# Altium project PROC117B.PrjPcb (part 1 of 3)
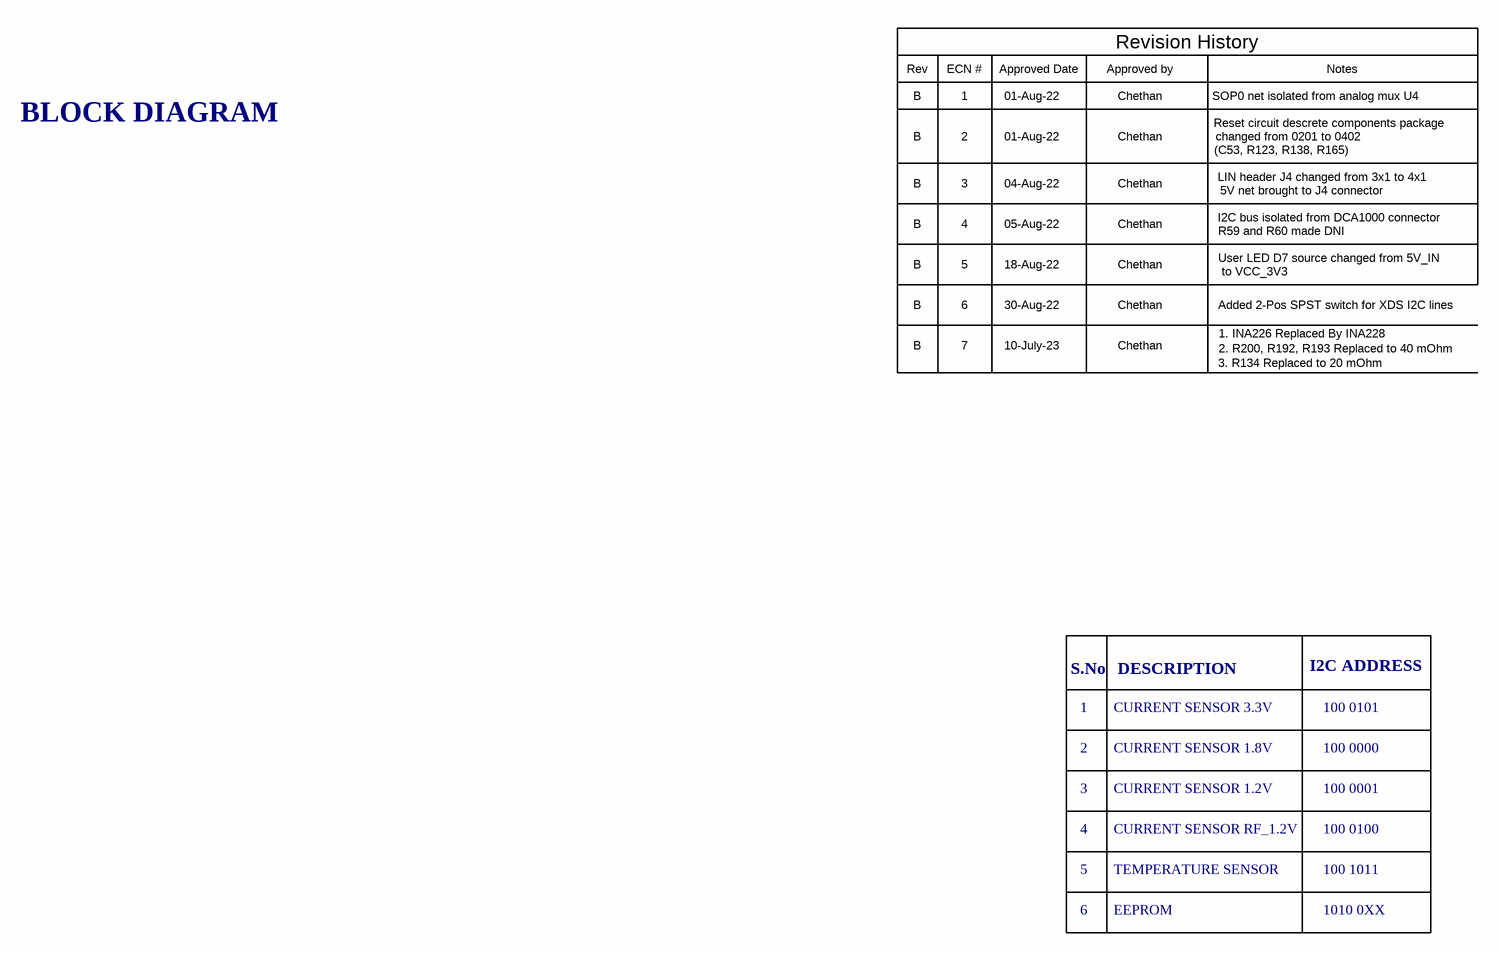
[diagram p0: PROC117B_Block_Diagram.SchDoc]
CopyrightYear: 2022; PCB_Layout: Mistral; PCB_Rev: B; PRJ_Customer: Public Release; PRJ_Engineer: Mistral; PRJ_Number: PROC117; PRJ_Title: xWRL6432BOOST; SCH_Rev: B; TechSupport: http://www.ti.com/support; TID: N/A
16 sheets, 457 parts. Net scope: flat (ports and power ports of the same name join across sheets).
Board file: PROC117B_PCB.PcbDoc
Sheets:
  PROC117B_Block_Diagram.SchDoc
  PROC117B_MUX_Block_Diagram.SchDoc
  PROC117B_Table_Of_Contents.SchDoc
  PROC117B_USB_PWR_DC_Jack_Switch.SchDoc
  PROC117B_DC_Regulators.SchDoc
  PROC117B_xWRL6432_Chip.SchDoc
  PROC117B_Decoupling_caps.SchDoc
  PROC117B_Temp_Current_sensors_EPROM.SchDoc
  PROC117B_QSPI_Flash_LVDS_Driver.SchDoc
  PROC117B_Analog_Mux_SOP_Ctrl.SchDoc
  PROC117B_XDS110_Interface_1A.SchDoc
  PROC117B_XDS110_Interface_1B.SchDoc
  PROC117B_CAN_LIN_PHY_Interface.SchDoc
  PROC117B_DCA1000_Connector_Reset.SchDoc
  PROC117B_LP_BP_Connector.SchDoc
  PROC117B_EVM_Hardware.SchDoc

## Sheet PROC117B_Block_Diagram.SchDoc: BLOCK DIAGRAM
size 431 x 279 mm; Date: Not shown in title block; ApprovedBy: Not shown in title block; CheckedBy: Not shown in title block; Author: Not shown in title block; CompanyName: Not shown in title block; DrawnBy: Mistral; Organization: Not shown in title block; Address1: Not shown in title block; Address2: Not shown in title block; Address3: Not shown in title block; Address4: Not shown in title block; DocumentNumber: 1; Revision: Use project parameter SCH_Rev; SheetNumber: 1; SheetTotal: 16; PageSetup: Record=PageOptions¦CenterHorizontal=True¦CenterVertical=True¦PrintScale=1.00¦XCorrection=1.00¦YCorrection=1.00¦PrintKind=0¦BorderSize=5000000¦LeftOffset=0¦BottomOffset=0¦Orientation=2¦PaperLength=1000¦PaperWidth=1000¦Scale=100¦PaperSource=15¦PrintQuality=600¦MediaType=1¦DitherType=10¦PaperKind=Letter¦PrintScaleMode=1

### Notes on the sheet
- Rev
- B
- ECN #
- 1
- 01-Aug-22
- Approved Date
- Approved by
- Chethan
- Revision History
- SOP0 net isolated from analog mux U4
- Notes
- BLOCK DIAGRAM
- 2
- (C53, R123, R138, R165)
- changed from 0201 to 0402
- Reset circuit descrete components package
- 3
- 4
- 04-Aug-22
- 05-Aug-22
- R59 and R60 made DNI
- 5V net brought to J4 connector
- LIN header J4 changed from 3x1 to 4x1
- I2C bus isolated from DCA1000 connector
- 5
- 6
- 18-Aug-22
- 30-Aug-22
- to VCC_3V3
- User LED D7 source changed from 5V_IN
- Added 2-Pos SPST switch for XDS I2C lines
- 7
- 10-July-23
- 3. R134 Replaced to 20 mOhm
- 1. INA226 Replaced By INA228
- 2. R200, R192, R193 Replaced to 40 mOhm
- S.No
- DESCRIPTION
- I2C ADDRESS
- CURRENT SENSOR 3.3V
- CURRENT SENSOR 1.8V
- 100 0000
- 100 0101
- CURRENT SENSOR 1.2V
- CURRENT SENSOR RF_1.2V
- 100 0001
- 100 0100
- TEMPERATURE SENSOR
- 100 1011
- EEPROM
- 1010 0XX

## Sheet PROC117B_MUX_Block_Diagram.SchDoc: MUX BLOCK DIAGRAM
size 431 x 279 mm; Date: Not shown in title block; ApprovedBy: Not shown in title block; CheckedBy: Not shown in title block; Author: Not shown in title block; CompanyName: Not shown in title block; DrawnBy: Mistral; Engineer: Not shown in title block; Organization: Not shown in title block; Address1: Not shown in title block; Address2: Not shown in title block; Address3: Not shown in title block; Address4: Not shown in title block; DocumentNumber: 2; Revision: Use project parameter SCH_Rev; SheetNumber: 2; SheetTotal: 16; PageSetup: Record=PageOptions¦CenterHorizontal=True¦CenterVertical=True¦PrintScale=1.00¦XCorrection=1.00¦YCorrection=1.00¦PrintKind=0¦BorderSize=5000000¦LeftOffset=0¦BottomOffset=0¦Orientation=2¦PaperLength=1000¦PaperWidth=1000¦Scale=100¦PaperSource=15¦PrintQuality=600¦MediaType=1¦DitherType=10¦PaperKind=Letter¦PrintScaleMode=1
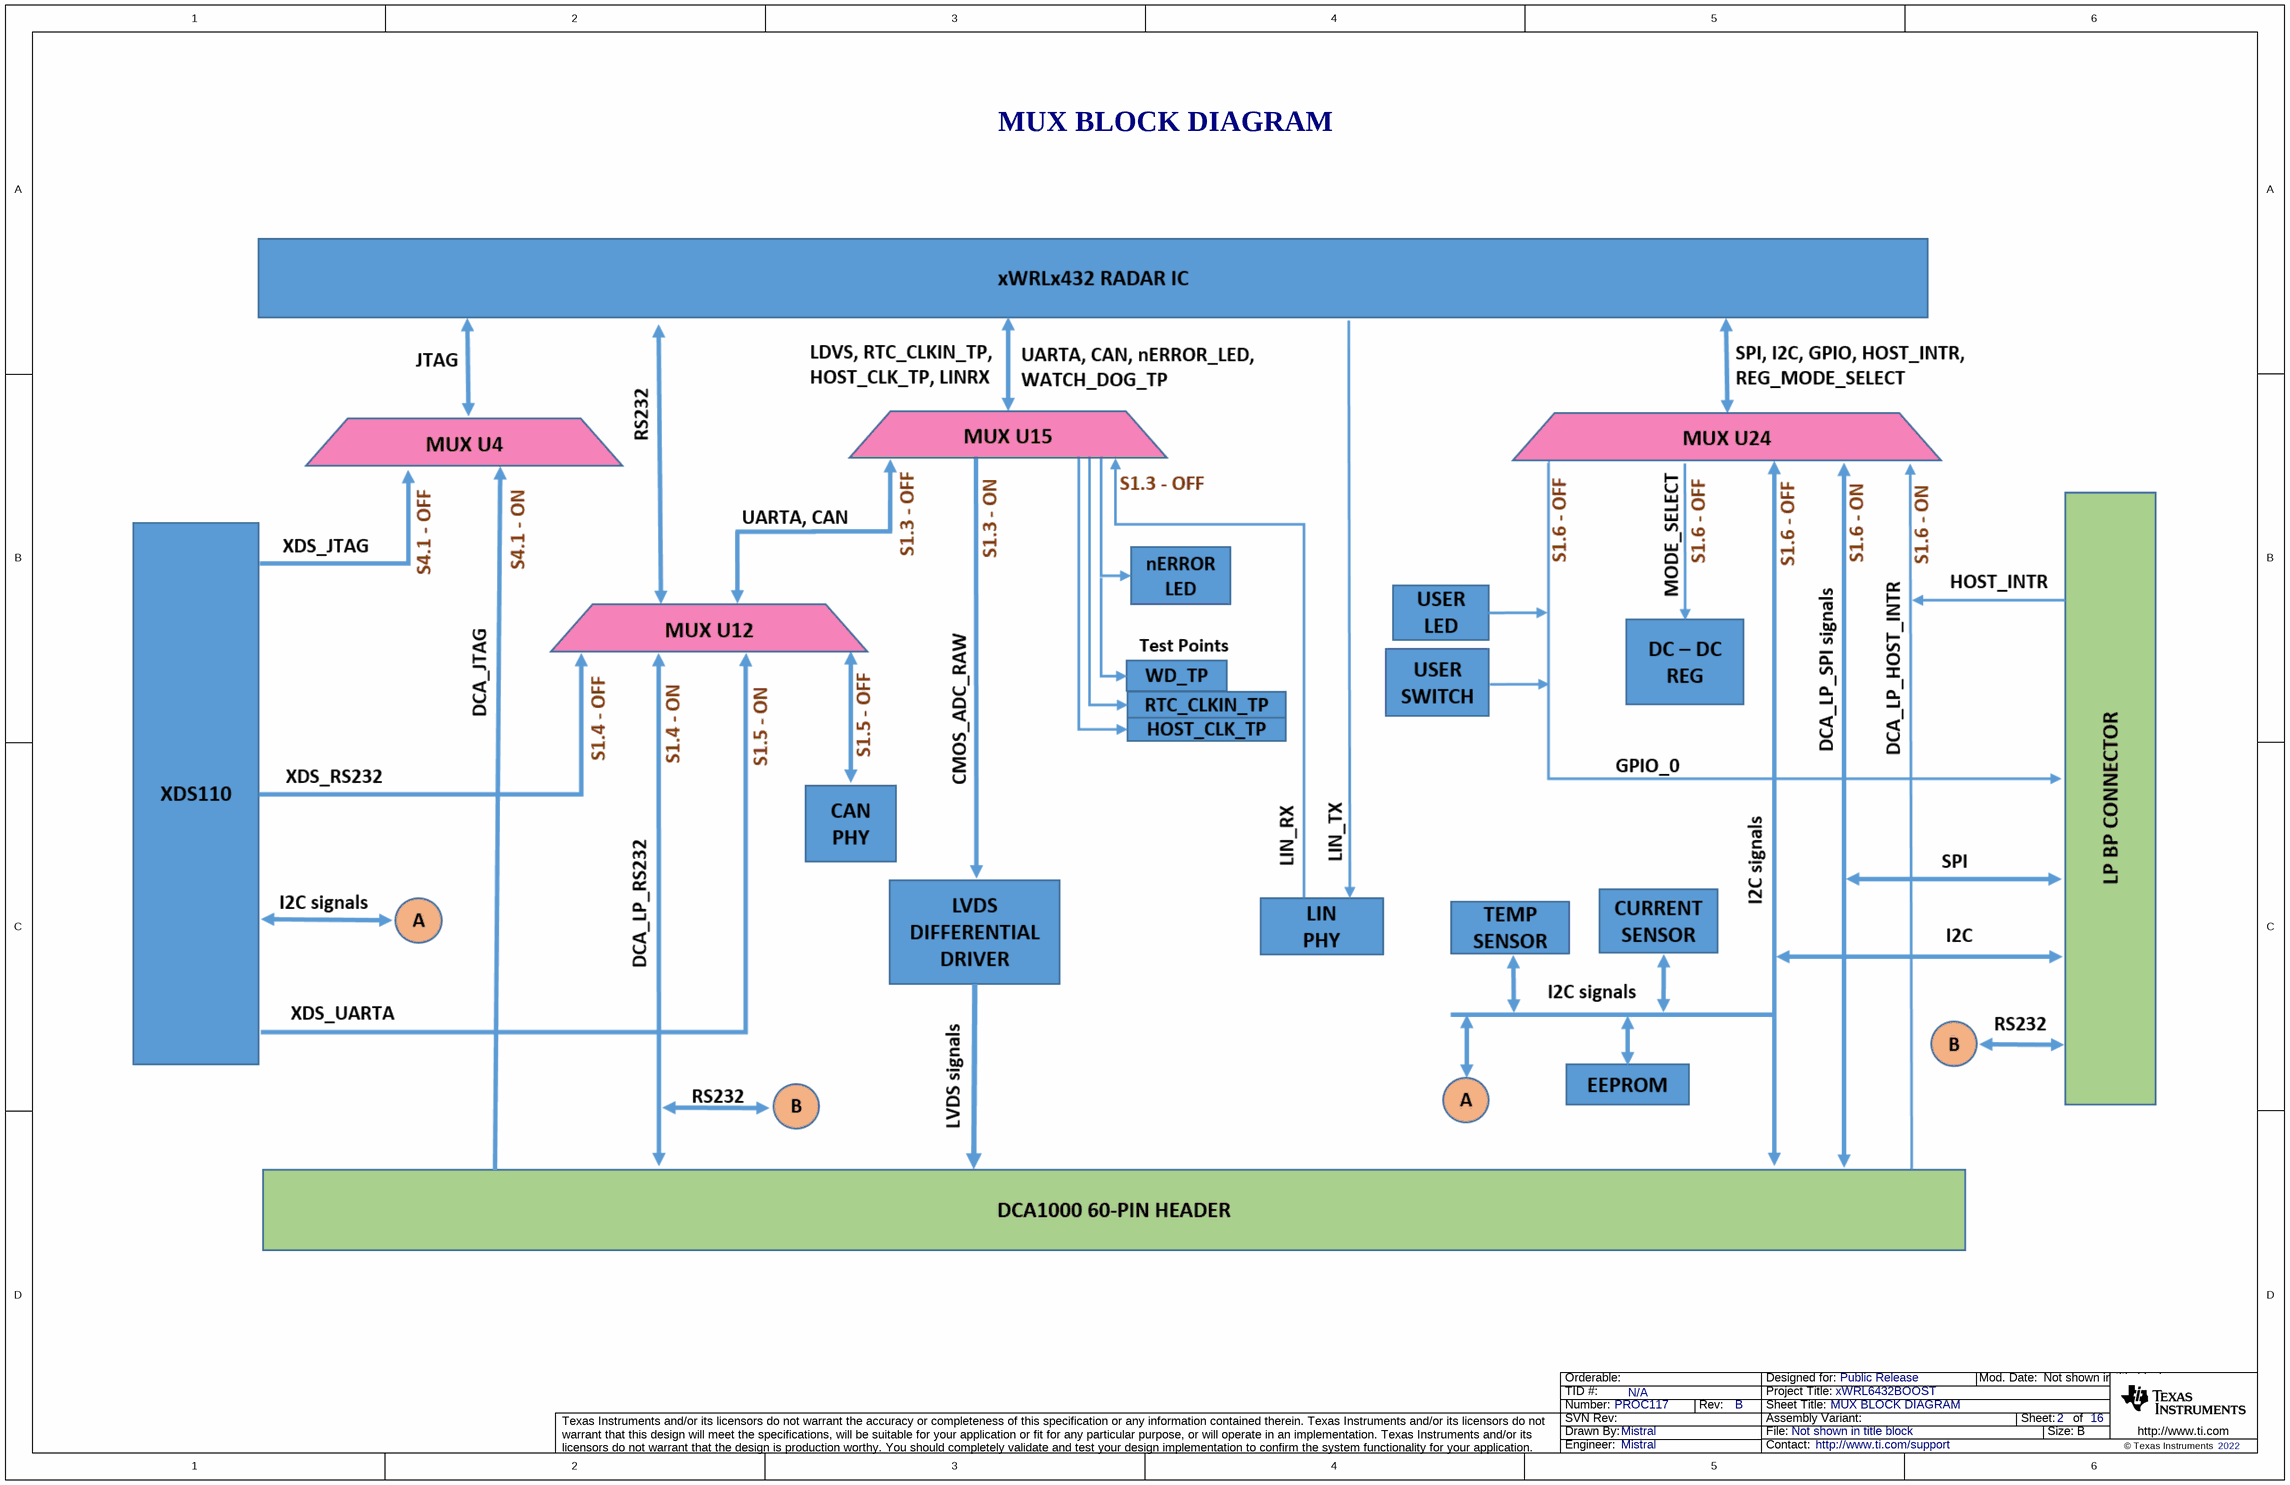
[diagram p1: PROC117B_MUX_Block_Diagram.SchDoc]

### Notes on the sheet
- MUX BLOCK DIAGRAM

## Sheet PROC117B_Table_Of_Contents.SchDoc: TABLE OF CONTENTS
size 431 x 279 mm; Date: Not shown in title block; ApprovedBy: Not shown in title block; CheckedBy: Not shown in title block; Author: Not shown in title block; CompanyName: Not shown in title block; DrawnBy: Mistral; Engineer: Not shown in title block; Organization: Not shown in title block; Address1: Not shown in title block; Address2: Not shown in title block; Address3: Not shown in title block; Address4: Not shown in title block; DocumentNumber: 3; Revision: Use project parameter SCH_Rev; SheetNumber: 3; SheetTotal: 16; PageSetup: Record=PageOptions¦CenterHorizontal=True¦CenterVertical=True¦PrintScale=1.00¦XCorrection=1.00¦YCorrection=1.00¦PrintKind=0¦BorderSize=5000000¦LeftOffset=0¦BottomOffset=0¦Orientation=2¦PaperLength=1000¦PaperWidth=1000¦Scale=100¦PaperSource=15¦PrintQuality=600¦MediaType=1¦DitherType=10¦PaperKind=Letter¦PrintScaleMode=1
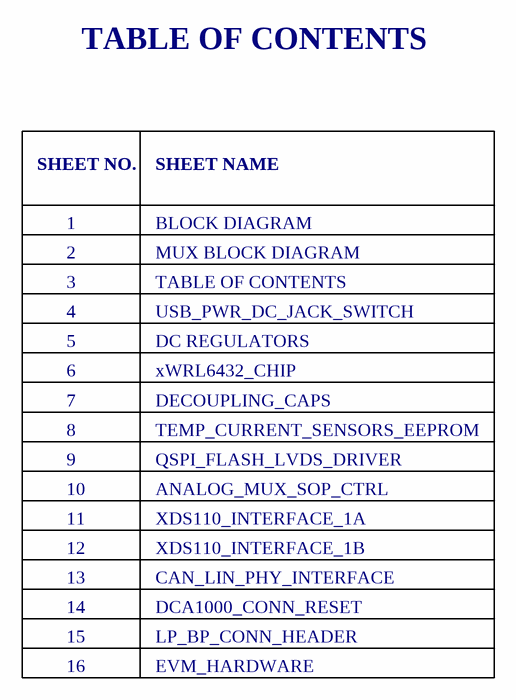
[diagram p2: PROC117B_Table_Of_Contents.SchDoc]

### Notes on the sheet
- TABLE OF CONTENTS
- SHEET NO.
- SHEET NAME
- 1
- 2
- 3
- BLOCK DIAGRAM
- MUX BLOCK DIAGRAM
- 4
- 5
- USB_PWR_DC_JACK_SWITCH
- DC REGULATORS
- 7
- 8
- 6
- DECOUPLING_CAPS
- TEMP_CURRENT_SENSORS_EEPROM
- xWRL6432_CHIP
- 9
- 10
- QSPI_FLASH_LVDS_DRIVER
- ANALOG_MUX_SOP_CTRL
- 11
- 12
- 13
- XDS110_INTERFACE_1B
- XDS110_INTERFACE_1A
- CAN_LIN_PHY_INTERFACE
- 14
- 15
- DCA1000_CONN_RESET
- LP_BP_CONN_HEADER
- 16
- EVM_HARDWARE

## Sheet PROC117B_USB_PWR_DC_Jack_Switch.SchDoc: USB_PWR_DC_JACK_SWITCH
size 431 x 279 mm; Date: Not shown in title block; ApprovedBy: Not shown in title block; CheckedBy: Not shown in title block; Author: Not shown in title block; CompanyName: Not shown in title block; DrawnBy: Mistral; Engineer: Not shown in title block; Organization: Not shown in title block; Address1: Not shown in title block; Address2: Not shown in title block; Address3: Not shown in title block; Address4: Not shown in title block; DocumentNumber: 4; Revision: Use project parameter SCH_Rev; SheetNumber: 4; SheetTotal: 16; PageSetup: Record=PageOptions¦CenterHorizontal=True¦CenterVertical=True¦PrintScale=1.00¦XCorrection=1.00¦YCorrection=1.00¦PrintKind=0¦BorderSize=5000000¦LeftOffset=0¦BottomOffset=0¦Orientation=2¦PaperLength=1000¦PaperWidth=1000¦Scale=100¦PaperSource=15¦PrintQuality=600¦MediaType=1¦DitherType=10¦PaperKind=Letter¦PrintScaleMode=1
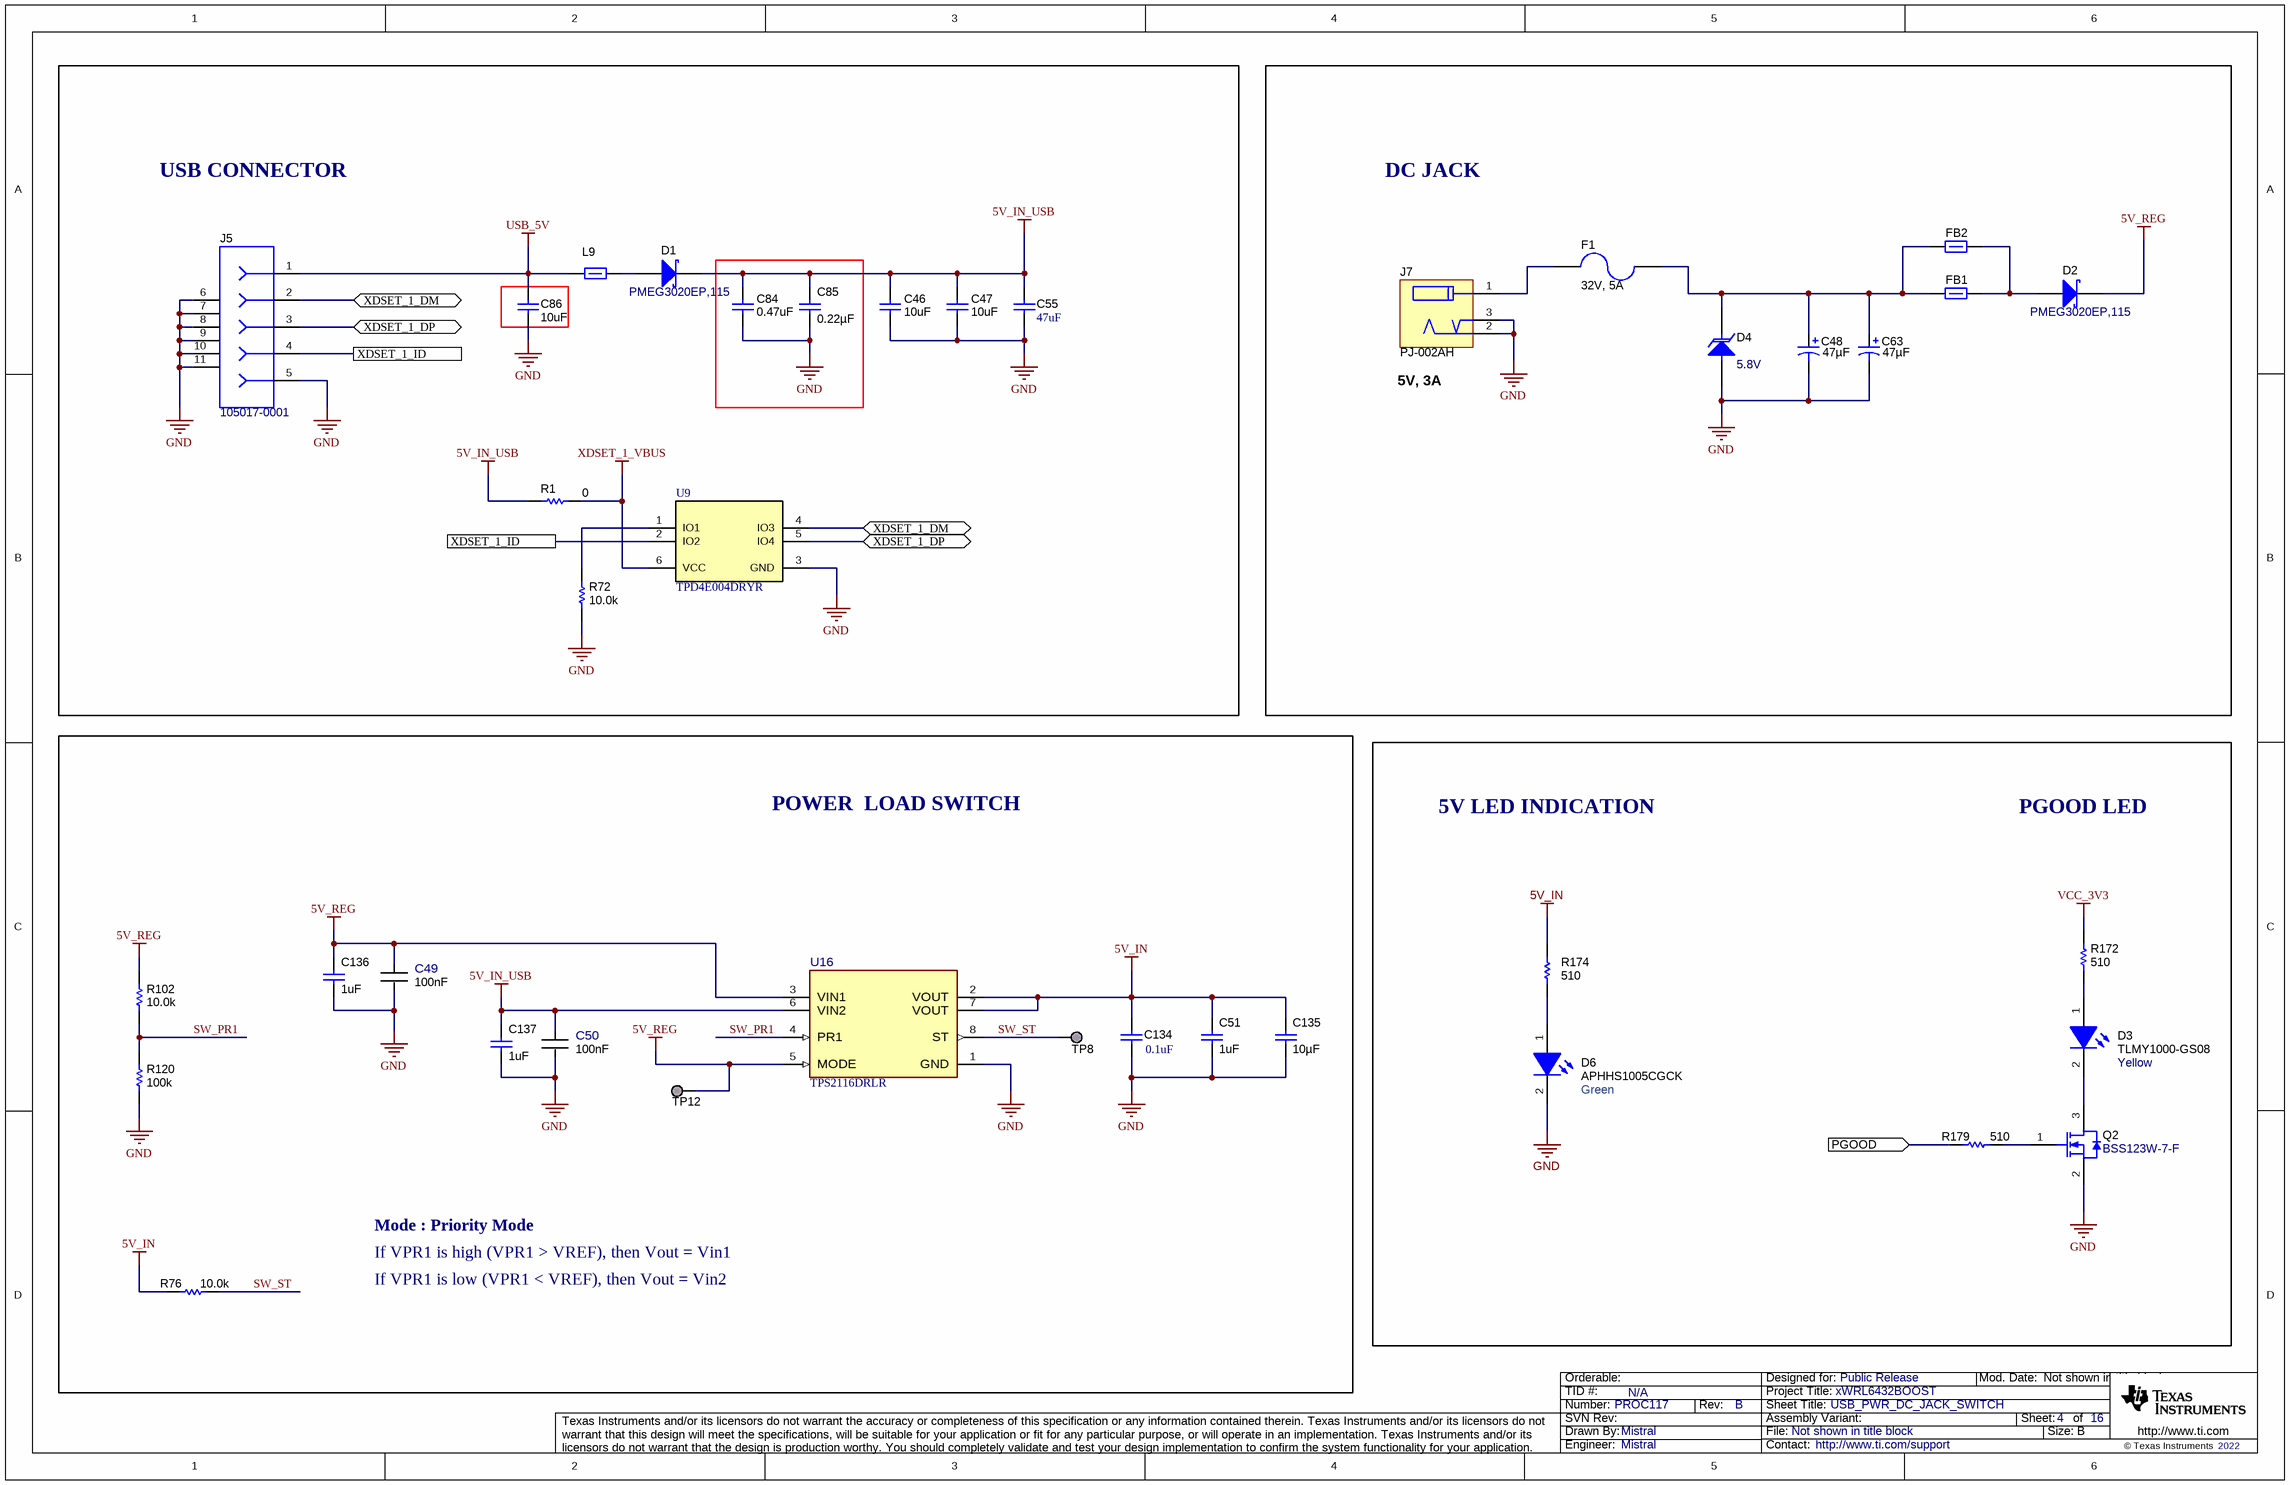
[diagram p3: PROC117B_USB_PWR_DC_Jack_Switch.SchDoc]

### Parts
C46  value 10uF  [0402_070]  (hidden comment: CL05A106MP5NUNC)
C47  value 10uF  [0402_070]  (hidden comment: CL05A106MP5NUNC)
C48  ValueDisplayed: 47µF  [3528-21]  (hidden comment: T491B476K010AT)
C49  value 100nF  [FP-GRM033R6YA104KE14D_0201 (0603 Metric)-IPC_C]  (hidden comment: GRM033R6YA104KE14D)
C50  value 100nF  [FP-GRM033R6YA104KE14D_0201 (0603 Metric)-IPC_C]  (hidden comment: GRM033R6YA104KE14D)
C51  ValueDisplayed: 1uF  [0402L]  (hidden comment: GRT155C81A105KE01D)
C55  ValueDisplayed: 47uF  [1206_180]  (hidden comment: GRM31CR61A476KE15L)
C63  ValueDisplayed: 47µF  [3528-21]  (hidden comment: T491B476K010AT)
C84  ValueDisplayed: 0.47uF  [0402L]  (hidden comment: GCM155C71A474KE36D)
C85  ValueDisplayed: 0.22µF  [0402L]  (hidden comment: GCM155R71C224KE02D)
C86  ValueDisplayed: 10uF  [0603S]  (hidden comment: GRT188R61A106KE13D)
C134  ValueDisplayed: 0.1uF  [0402]  (hidden comment: GCM155R71H104KE02D)
C135  Cap_F: 10µF  [0603]  (hidden comment: GRM188Z71A106MA73D)
C136  ValueDisplayed: 1uF  [0402L]  (hidden comment: GRT155C81A105KE01D)
C137  ValueDisplayed: 1uF  [0402L]  (hidden comment: GRT155C81A105KE01D)
D1  PMEG3020EP,115  [SOD-128]
D2  PMEG3020EP,115  [SOD-128]
D3  TLMY1000-GS08  value Yellow  [TLMx1000_Yellow]
D4  value 5.8V  [SMB]  (hidden comment: SZP6SMB6.8AT3G)
D6  APHHS1005CGCK  Color: Green  [APHHS1005_Green]
F1  32V, 5A  [1206]
FB1  BLM21PG300SH1D  [0805_HV]  (value not drawn)
FB2  BLM21PG300SH1D  [0805_HV]  (value not drawn)
J5  105017-0001  [CONN_105017-0001]
J7  PJ-002AH  [CUI_PJ-002AH]
L9  BLM15PD300SZ1D  [0402L]  (value not drawn)
Q2  BSS123W-7-F  [SOT-323]
R1  ValueDisplayed: 0  [0603]  (hidden comment: MCT06030Z0000ZP500)
R72  ValueDisplayed: 10.0k  [0402L]  (hidden comment: CRCW040210K0FKED)
R76  ValueDisplayed: 10.0k  [0402L]  (hidden comment: CRCW040210K0FKED)
R102  ValueDisplayed: 10.0k  [0402L]  (hidden comment: CRCW040210K0FKED)
R120  value 100k  [0201L]  (hidden comment: CRCW0201100KFKED)
R172  ValueDisplayed: 510  [0402L]  (hidden comment: ERJ-2GEJ511X)
R174  value 510  [0201L]  (hidden comment: RC0201JR-07510RL)
R179  ValueDisplayed: 510  [0402L]  (hidden comment: ERJ-2GEJ511X)
TP8  TESTPOINT  [TP_25MIL-SMT]  (value not drawn)  (no BOM)
TP12  TESTPOINT  [TP_25MIL-SMT]  (value not drawn)  (no BOM)
U9  TPD4E004DRYR  [DRY0006A]
U16  TPS2116DRLR  [DRL0008A-MFG]

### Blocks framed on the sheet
USB CONNECTOR: C46 C47 C55 C84-C86 D1 J5 L9 R1 R72 U9
DC JACK: C48 C63 D2 D4 F1 FB1 FB2 J7
POWER  LOAD SWITCH: C49-C51 C134-C137 R76 R102 R120 TP8 TP12 U16

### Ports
PGOOD (in), XDSET_1_DM (bidir), XDSET_1_DP (bidir), XDSET_1_ID

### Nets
5V_IN: C51.1 C134.1 C135.1 R76.2 R174.1 U16.2(VOUT) U16.7(VOUT)
5V_IN_USB: C46.2 C47.1 C50.1 C55.1 C84.1 C85.2 C137.1 D1.1(K) R1.2 U16.6(VIN2)
5V_REG: C49.1 C136.1 D2.1(K) R102.2 TP12.1 U16.3(VIN1) U16.5(MODE)
GND: C46.1 C47.2 C48.2(-) C49.2 C50.2 C51.2 C55.2 C63.2(-) C84.2 C85.1 C86.1 C134.2 C135.2 C136.2 C137.2 D4.2(A) D6.2(K) J5.5 J5.6 J5.7 J5.8 J5.9 J5.10 J5.11 J7.2 J7.3 Q2.2(S) R72.1 R120.1 U9.3(GND) U16.1(GND)
USB_5V: C86.2 J5.1 L9.1
VCC_3V3: R172.2
XDSET_1_VBUS: R1.1 U9.6(VCC)
PGOOD: R179.1 ; port PGOOD
SW_PR1: R102.1 R120.2 U16.4(PR1)
SW_ST: R76.1 TP8.1 U16.8(ST)
XDSET_1_DM: J5.2 U9.4(IO3) ; port XDSET_1_DM
XDSET_1_DP: J5.3 U9.5(IO4) ; port XDSET_1_DP
XDSET_1_ID: J5.4 U9.2(IO2) ; port XDSET_1_ID
NetC48_1: C48.1(+) C63.1(+) D4.1(K) F1.1 FB1.1 FB2.1
NetD1_2: D1.2(A) L9.2
NetD2_2: D2.2(A) FB1.2 FB2.2
NetD3_1: D3.1(A) R172.1
NetD3_2: D3.2(K) Q2.3(D)
NetD6_1: D6.1(A) R174.2
NetF1_2: F1.2 J7.1
NetQ2_1: Q2.1(G) R179.2
NetR72_2: R72.2 U9.1(IO1)

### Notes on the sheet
- (near J7) 5V, 3A
- 5V LED INDICATION
- PGOOD LED
- Mode : Priority Mode
- If VPR1 is high (VPR1 > VREF), then Vout = Vin1
- If VPR1 is low (VPR1 < VREF), then Vout = Vin2

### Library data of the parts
C46 C47 = CMP-0006339-4: CAP, CERM, 10 uF, 10 V, +/- 20%, X5R, 0402; Manufacturer: Samsung Electro-Mechanics; AEC Category: Q200; AEC Qualified: N; Cap_Case: 0402; Cap_F: 10µF; SizeArea_mm2: 0.5; SizeAreaWB_mm2: 3; SizeX_mm: 1; SizeZ_mm: 0.6; TaMax_C: 85°C; TaMin_C: -55°C; U/M: EA; Value1: Unknown; Value2: 10V
C48 C63 = CMP-0078216-1: CAP, TA, 47 µF, 10 V, +/- 10%, SMD; Manufacturer: Kemet; TaMin_C: -55°C; Polarized: Y; SizeAreaWB_mm2: 17.1; Value: 47uF; TaMax_C: 125°C; SizeZ_mm: 2.1; SizeX_mm: 3.5; SizeY_mm: 2.8; Value2: 10V; SizeArea_mm2: 9.8; CompType: Capacitor; AEC Qualified: N; AEC Category: Q200
C49 C50 = CMP-0086440-1: Cap Ceramic 0.1uF 35V X5R 10% Pad SMD 0201 85C T/R; Manufacturer: Murata Electronics North America; AEC Qualified: No; SizeZ_mm: 0.33mm; Symbol Name: SYM-GRM033R6YA104KE14D; TempCo: 15%
C51 C136 C137 = CMP-0006272-2: CAP, CERM, 1 uF, 10 V, +/- 10%, X6S, 0402; Manufacturer: TDK; Polarized: N; Value: 1uF; U/M: EA; Cap_F: 1µF; Value1: Unknown; VDC_V: 16V; TempCo: X5R; TaMin_C: -55°C; TaMax_C: 85°C; Cap_Case: 0402; SizeArea_mm2: 0.5; SizeAreaWB_mm2: 3; SizeX_mm: 1; SizeZ_mm: 0.6; AEC Category: Q200
C55 = CMP-0008944-2: CAP, CERM, 47 uF, 10 V, +/- 10%, X5R, 1206; Manufacturer: MuRata; TaMin_C: -55°C; Polarized: N; SizeAreaWB_mm2: 10.92; Value1: Unknown; U/M: EA; Value: 47uF; TaMax_C: 85°C; SizeZ_mm: 1.8; SizeX_mm: 3.2; SizeY_mm: 1.6; Cap_Case: 1206; Value2: 10V; SizeArea_mm2: 5.12; Cap_F: 47µF; AEC Category: Q200
C84 = CMP-0064967-2: CAP, CERM, 0.47 uF, 10 V,+/- 10%, X7S, 0402; Manufacturer: MuRata; Polarized: N; Value: 0.47uF; U/M: EA; Cap_F: 470nF; Value1: Unknown; VDC_V: 10V; TaMin_C: -55°C; TaMax_C: 125°C; Cap_Case: 0402; SizeArea_mm2: 0.5; SizeAreaWB_mm2: 3; SizeX_mm: 1; SizeZ_mm: 0.6; AEC Category: Q200
C85 = CMP-0078265-1: CAP, CERM, 0.22 µF, 16 V,+/- 10%, X7R, AEC-Q200 Grade 1, 0402; Manufacturer: MuRata; TaMin_C: -55°C; Polarized: N; SizeAreaWB_mm2: 3; U/M: EA; Value: 0.22uF; TaMax_C: 125°C; SizeZ_mm: 0.6; SizeX_mm: 1; SizeY_mm: 0.5; Cap_Case: 0402; Value2: 16V; CompType: Capacitor; AEC Qualified: Y; Cap_F: 220nF; AEC Category: Q200
C86 = CMP-0007497-5: CAP, CERM, 10 uF, 10 V, +/- 10%, X5R, 0603; Manufacturer: MuRata; Polarized: N; Value: 10uF; U/M: EA; Cap_F: 10µF; Tolerance_%: 20%; Value1: Unknown; VDC_V: 10V; TempCo: X7R; TaMin_C: -55°C; TaMax_C: 125°C; Cap_Case: 0603; SizeArea_mm2: 1.28; SizeAreaWB_mm2: 4.68; SizeX_mm: 1.6; SizeY_mm: 0.8; SizeZ_mm: 1; AEC Category: Q200
C134 = CMP-0006356-2: CAP, CERM, 0.1 uF, 50 V, +/- 10%, X7R, AEC-Q200 Grade 1, 0402; Manufacturer: MuRata; TaMin_C: -55°C; Polarized: N; SizeAreaWB_mm2: 3; Value1: Unknown; U/M: EA; Value: 0.1uF; TaMax_C: 125°C; SizeZ_mm: 0.6; SizeX_mm: 1; SizeY_mm: 0.5; Value2: 50V; AEC Qualified: Y; Cap_F: 100nF; AEC Category: Q200
C135 = CMP-0007497-5: CAP, CERM, 10 uF, 10 V, +/- 20%, X7R, 0603; Manufacturer: MuRata; TaMin_C: -55°C; Polarized: N; SizeAreaWB_mm2: 4.68; Value1: Unknown; U/M: EA; Value: 10uF; TaMax_C: 125°C; SizeZ_mm: 1; SizeX_mm: 1.6; SizeY_mm: 0.8; Value2: 10V; SizeArea_mm2: 1.28; AEC Category: Q200
D1 D2 = CMP-0078758-2: Diode, Schottky, 30 V, 2 A, AEC-Q101, SOD-128; Manufacturer: Nexperia; Value2: 0.36V; SizeAreaWB_mm2: 19.6; Io_A: 2A; Value: 30V; AEC Qualified: Y; TJmax_C: 150°C; SizeX_mm: 4.6; AEC Category: Q101; SizeY_mm: 2.5; SizeArea_mm2: 11.5; Vf_V: 3.6dV; SizeZ_mm: 1.1
D3 = CMP-0078196-2: LED, Yellow, SMD; Manufacturer: Vishay-Semiconductor; Tjmax_C: 120°C; SizeAreaWB_mm2: 4.68; Vr_V: 6V; Power_TotalModule: 40mW; Angle: 160; SizeArea_mm2: 1.28; Ir_A: 10µA; SizeZ_mm: 0.65; Io_A: 2mA; Vf_V: 1.8V; SizeY_mm: 0.8; Value1: .04W; SizeX_mm: 1.6; Type: AlInGaP
D4 = CMP-0078243-3: Diode, TVS, Uni, 5.8 V, 10.5 Vc, AEC-Q101, SMB; Manufacturer: Littelfuse; SizeAreaWB_mm2: 44.156; Value1: 0.55W; RJA_CperW: 226; SizeZ_mm: 2.6; SizeX_mm: 5.6; SizeY_mm: 3.81; SizeArea_mm2: 21.336; AEC Qualified: Y; AEC Category: Q101; Vc: 10.5V
D6 = CMP-0067682-2: LED, Green, SMD; Manufacturer: Kingbright; Angle: 120.0; Power_TotalModule: 75mW; SizeZ_mm: 0.6; Vf_V: 2.1V; Vr_V: 5V; Io_A: 20mA; Ir_A: 10µA; SizeArea_mm2: 0.5; SizeAreaWB_mm2: 3.0; SizeX_mm: 1.0; Tjmax_C: 85°C; Value1: 0.075W
F1 = CMP-0003458-2: Fuse, 5 A, 32VAC/VDC, SMD; Manufacturer: Littelfuse; PartNumber: 0440005.WR; SizeAreaWB_mm2: 10.92; Interrupt_AC: 50A; SizeZ_mm: 1.35; SizeX_mm: 3.2; SizeY_mm: 1.6; SizeArea_mm2: 5.12; Rtyp_Ohm: 0.012; MeltingTyp: 4.761
FB1 = CMP-0003364-1: Ferrite Bead, 30 ohm @ 100 MHz, 4 A, 0805; Manufacturer: MuRata; ZTyp@100MHz_Ohm: 30; SizeAreaWB_mm2: 6.75; DCR_ohm: 0.014; Value1: 0.014 ohm; Value: 30 ohm; Imax_A: 4A; SizeZ_mm: 1.45; SizeX_mm: 2; SizeY_mm: 1.25; SizeArea_mm2: 2.5; INSTALLATION: DNP
FB2 = CMP-0003364-1: Ferrite Bead, 30 ohm @ 100 MHz, 4 A, 0805; Manufacturer: MuRata; ZTyp@100MHz_Ohm: 30; SizeAreaWB_mm2: 6.75; DCR_ohm: 0.014; Value1: 0.014 ohm; Value: 30 ohm; Imax_A: 4A; SizeZ_mm: 1.45; SizeX_mm: 2; SizeY_mm: 1.25; SizeArea_mm2: 2.5
J5 = CMP-0055293-1: Connector, Receptacle, Micro-USB Type B, R/A, Bottom Mount SMT; Manufacturer: Molex; CNHeader: FALSE; CompType: USB; CT: TRUE; Gender: Female; Green_Lifecycle: Active; Green_REACh: Passed
J7 = CMP-0078270-1: DC POWER JACK, R/A, TH; Manufacturer: CUI Inc.; Gender: Female; Cert_UL: Y; Current_A: 5A; Voltage_V: 4.5-5.5V; Green_REACh: Incomplete; Green_Lifecycle: Not Set
L9 = CMP-0078934-1: Inductor, Ferrite Bead, Ferrite, 2.2 A, 0.035 ohm, AEC-Q200 Grade 1, SMD; Manufacturer: MuRata; AEC Category: Q200; AEC Grade: 1; AEC Qualified: Y; DCR_ohm: 0.035; Imax_A: 2.2A; SizeArea_mm2: 0.5; SizeAreaWB_mm2: 3; SizeZ_mm: 0.6
Q2 = CMP-0000948-2: MOSFET, N-CH, 100 V, 0.17 A, SOT-323; Alternate Manufacturer: None; Manufacturer: Diodes Inc.; SizeZ_mm: 1.1; ChType: N; Value1: 1; VdsMax_V: 100V; SizeX_mm: 2.2; Vgs_V: 20V; Value: 100V; Rdson45_ohm: 10; SizeArea_mm2: 4.84; AEC Category: Q101; IdsMax_A: 1.7dA; SizeAreaWB_mm2: 10.24; U/M: EA
R1 = CMP-0025884-3: RES, 0, 5%, 0.125 W, 0603; Manufacturer: Vishay/Beyschlag; Power_W: 125mW; TempCo: ppm/C; Value_Code: 0000; U/M: EA; Value: 0; EIA_Code: E24; SizeX_mm: 1.6; SizeY_mm: 0.8; SizeZ_mm: 1; Value2: 0.125W; SizeArea_mm2: 1.28; AEC Qualified: N; AEC Category: Q200
R72 R76 R102 = CMP-0025958-3: RES, 10.0 k, 1%, 0.063 W, AEC-Q200 Grade 0, 0402; Manufacturer: Vishay-Dale; Power_W: 63mW; TempCo: 100 ppm/C; Value_Code: 10k0; Value: 10.0k; EIA_Code: E96; Res_ohm: 10k; SizeX_mm: 1; SizeY_mm: 0.5; SizeZ_mm: 0.6; Value2: 0.063W; AEC Qualified: Y; VDC_V: 50V; AEC Category: Q200; AEC Grade: 0
R120 = CMP-0027261-3: RES, 100 k, 1%, 0.05 W, 0201; Manufacturer: Vishay-Dale; AEC Category: Q200; AEC Qualified: N; EIA_Code: E96; Power_W: 50mW; SizeArea_mm2: 0.18; SizeX_mm: 0.6; SizeY_mm: 0.3; SizeZ_mm: 0.26; TempCo: 100 ppm/C; Value2: 0.05W; VDC_V: 30V
R172 R179 = CMP-0078212-1: RES, 510, 5%, 0.1 W, AEC-Q200 Grade 0, 0402; Manufacturer: Panasonic; Value_Code: 510R; SizeArea_mm2: 0.5; AEC Qualified: Y; AEC Category: Q200; Value: 510; SizeZ_mm: 0.6; EIA_Code: E24; TempCo: 200 ppm/C; AEC Grade: 0; Power_W: 100mW; VDC_V: 50V; Value2: 0.1W; U/M: EA; SizeX_mm: 1
R174 = CMP-0027137-1: RES, 510, 5%, 0.05 W, 0201; Manufacturer: Yageo America; AEC Category: Q200; AEC Qualified: N; EIA_Code: E24; Power_W: 50mW; SizeArea_mm2: 0.18; SizeX_mm: 0.6; SizeY_mm: 0.3; SizeZ_mm: 0.26; TempCo: 200 ppm/C; U/M: EA; Value2: 0.05W; Value_Code: 510R; VDC_V: 25V
TP8 TP12 = CMP-0078143-3: TEST POINT.  No entry in BOM.
U9 = CMP-0043115-3: 4-Channel ESD Protection Array for High-Speed Data Interfaces, DRY0006A (USON-6); Manufacturer: Texas Instruments; IO Leakage Current(nA): 1; USB High Speed: TRUE; IO Capacitance(Typ)(pF): 1.6; Eco-Plan: Green (RoHS & no Sb/Br); IEC 61000-4-2 Contact(+/- kV): 8; Breakdown Voltage(Min)(V): 6; IEC 61000-4-2 Air-Gap(+/- kV): 12; AEC Category: Q200; AEC Qualified: N; CompType: IC; SizeAreaWB_mm2: 4.9; SizeArea_mm2: 1.45; SizeX_mm: 1.0; SizeZ_mm: 0.6; Rating: Catalog
U16 = CMP-0088593-2: 1.6 V to 5 V, 2.5-A Low IQ Power Mux With Manual and Automatic Switchover; Manufacturer: Texas Instruments; Max Supply Voltage: 5.5V; TaMax_C: +125°C; Output Voltage: 0-5.5V; CompType: IC; Min Supply Voltage: 1.6V; TaMin_C: -55°C; SizeZ_mm: 0.6mm; AEC Category: Q200; Nominal Supply Current: 0.5-1uA; Number Of Outputs: 1; Standoff Height: 0mm; AEC Qualified: No

## Sheet PROC117B_DC_Regulators.SchDoc: DC_REGULATORS
size 431 x 279 mm; Date: Not shown in title block; ApprovedBy: Not shown in title block; CheckedBy: Not shown in title block; Author: Not shown in title block; CompanyName: Not shown in title block; DrawnBy: Mistral; Engineer: Not shown in title block; Organization: Not shown in title block; Address1: Not shown in title block; Address2: Not shown in title block; Address3: Not shown in title block; Address4: Not shown in title block; DocumentNumber: 5; Revision: Use project parameter SCH_Rev; SheetNumber: 5; SheetTotal: 16; PageSetup: Record=PageOptions¦CenterHorizontal=True¦CenterVertical=True¦PrintScale=1.00¦XCorrection=1.00¦YCorrection=1.00¦PrintKind=0¦BorderSize=5000000¦LeftOffset=0¦BottomOffset=0¦Orientation=2¦PaperLength=1000¦PaperWidth=1000¦Scale=100¦PaperSource=15¦PrintQuality=600¦MediaType=1¦DitherType=10¦PaperKind=Letter¦PrintScaleMode=1
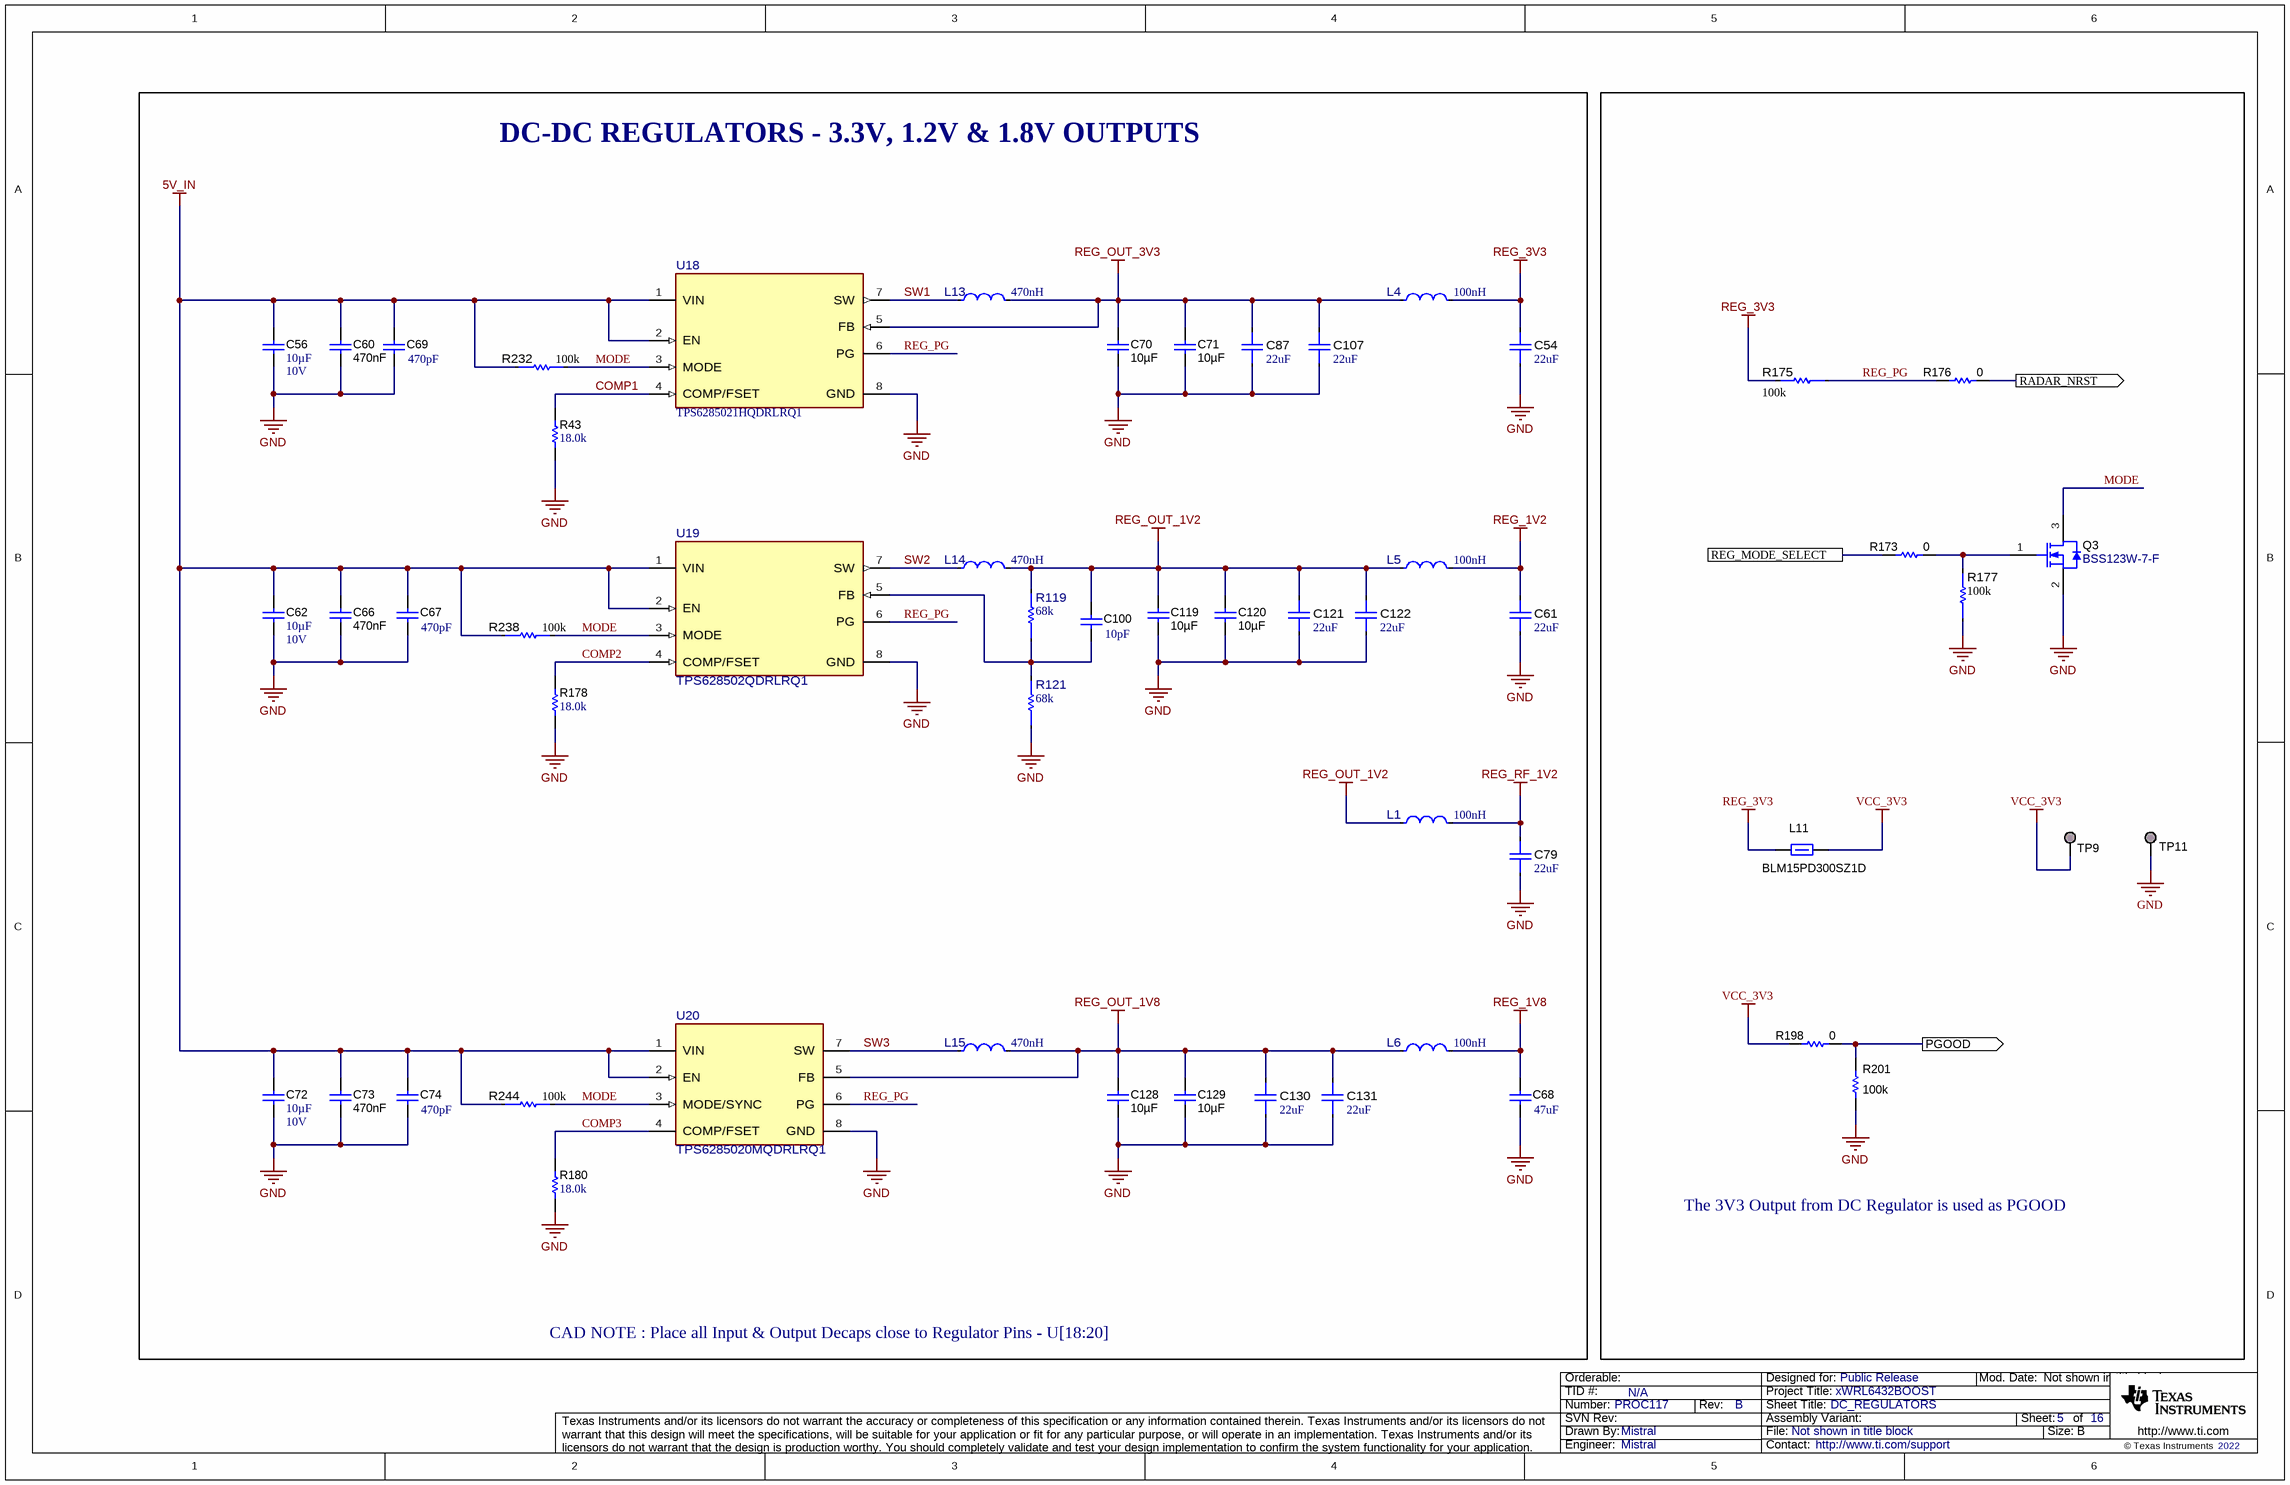
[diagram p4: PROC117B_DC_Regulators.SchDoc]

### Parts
C54  ValueDisplayed: 22uF  [FP-GRM31CR70J226ME19K_1206-MFG]  (hidden comment: GRM31CR70J226ME19K)
C56  Cap_F: 10µF  VDC_V: 10V  [0603_HV]  (hidden comment: GRM188Z71A106MA73D)
C60  Cap_F: 470nF  [0603S]  (hidden comment: GRM188R71C474KA88D)
C61  ValueDisplayed: 22uF  [FP-GRM31CR70J226ME19K_1206-MFG]  (hidden comment: GRM31CR70J226ME19K)
C62  Cap_F: 10µF  VDC_V: 10V  [0603_HV]  (hidden comment: GRM188Z71A106MA73D)
C66  Cap_F: 470nF  [0603S]  (hidden comment: GRM188R71C474KA88D)
C67  ValueDisplayed: 470pF  [0402L]  (hidden comment: GRM1555C1H471JA01D)
C68  ValueDisplayed: 47uF  [1206_180]  (hidden comment: GRM31CR60J476ME19L)
C69  ValueDisplayed: 470pF  [0402L]  (hidden comment: GRM1555C1H471JA01D)
C70  Cap_F: 10µF  [0603]  (hidden comment: GRM188Z71A106MA73D)
C71  Cap_F: 10µF  [0603]  (hidden comment: GRM188Z71A106MA73D)
C72  Cap_F: 10µF  VDC_V: 10V  [0603_HV]  (hidden comment: GRM188Z71A106MA73D)
C73  Cap_F: 470nF  [0603S]  (hidden comment: GRM188R71C474KA88D)
C74  ValueDisplayed: 470pF  [0402L]  (hidden comment: GRM1555C1H471JA01D)
C79  ValueDisplayed: 22uF  [FP-GRM31CR70J226ME19K_1206-MFG]  (hidden comment: GRM31CR70J226ME19K)
C87  ValueDisplayed: 22uF  [FP-GRM31CR70J226ME19K_1206-MFG]  (hidden comment: GRM31CR70J226ME19K)
C100  ValueDisplayed: 10pF  [0402]  (hidden comment: CGA2B2C0G1H100D050BA)
C107  ValueDisplayed: 22uF  [FP-GRM31CR70J226ME19K_1206-MFG]  (hidden comment: GRM31CR70J226ME19K)
C119  Cap_F: 10µF  [0603]  (hidden comment: GRM188Z71A106MA73D)
C120  Cap_F: 10µF  [0603]  (hidden comment: GRM188Z71A106MA73D)
C121  ValueDisplayed: 22uF  [FP-GRM31CR70J226ME19K_1206-MFG]  (hidden comment: GRM31CR70J226ME19K)
C122  ValueDisplayed: 22uF  [FP-GRM31CR70J226ME19K_1206-MFG]  (hidden comment: GRM31CR70J226ME19K)
C128  Cap_F: 10µF  [0603]  (hidden comment: GRM188Z71A106MA73D)
C129  Cap_F: 10µF  [0603]  (hidden comment: GRM188Z71A106MA73D)
C130  ValueDisplayed: 22uF  [FP-GRM31CR70J226ME19K_1206-MFG]  (hidden comment: GRM31CR70J226ME19K)
C131  ValueDisplayed: 22uF  [FP-GRM31CR70J226ME19K_1206-MFG]  (hidden comment: GRM31CR70J226ME19K)
L1  Ind_H: 100nH  [FP-LQM2MPZR10MJHL_0806 (2016)-MFG]  (hidden comment: LQM2MPZR10MJHL)
L4  Ind_H: 100nH  [FP-LQM2MPZR10MJHL_0806 (2016)-MFG]  (hidden comment: LQM2MPZR10MJHL)
L5  Ind_H: 100nH  [FP-LQM2MPZR10MJHL_0806 (2016)-MFG]  (hidden comment: LQM2MPZR10MJHL)
L6  Ind_H: 100nH  [FP-LQM2MPZR10MJHL_0806 (2016)-MFG]  (hidden comment: LQM2MPZR10MJHL)
L11  BLM15PD300SZ1D  [0402L]
L13  Ind_H: 470nH  [FP-DFE201210U-R47M=P2_0805 (2012)-MFG]  (hidden comment: DFE201210U-R47M=P2)
L14  Ind_H: 470nH  [FP-DFE201210U-R47M=P2_0805 (2012)-MFG]  (hidden comment: DFE201210U-R47M=P2)
L15  Ind_H: 470nH  [FP-DFE201210U-R47M=P2_0805 (2012)-MFG]  (hidden comment: DFE201210U-R47M=P2)
Q3  BSS123W-7-F  [SOT-323]
R43  ValueDisplayed: 18.0k  [0402L]  (hidden comment: CRCW040218K0FKED)
R119  Res_ohm: 68k  [FP-RMCF0402FT68K0_0402-MFG]  (hidden comment: RMCF0402FT68K0)
R121  Res_ohm: 68k  [FP-RMCF0402FT68K0_0402-MFG]  (hidden comment: RMCF0402FT68K0)
R173  Res_ohm: 0  [FP-RC0201JR-070RL_0201 (0603 Metric)-IPC_C]  (hidden comment: RC0201JR-070RL)
R175  Res_ohm: 100k  [FP-CRCW0402100KFKEDC_0402-IPC_B]  (hidden comment: CRCW0402100KFKEDC)
R176  Res_ohm: 0  [FP-RC0201JR-070RL_0201 (0603 Metric)-IPC_C]  (hidden comment: RC0201JR-070RL)
R177  Res_ohm: 100k  [FP-CRCW0402100KFKEDC_0402-IPC_B]  (hidden comment: CRCW0402100KFKEDC)
R178  ValueDisplayed: 18.0k  [0402L]  (hidden comment: CRCW040218K0FKED)
R180  ValueDisplayed: 18.0k  [0402L]  (hidden comment: CRCW040218K0FKED)
R198  Res_ohm: 0  [FP-RC0201JR-070RL_0201 (0603 Metric)-MFG]  (hidden comment: RC0201JR-070RL)
R201  value 100k  [0201L]  (hidden comment: CRCW0201100KFKED)
R232  Res_ohm: 100k  [FP-CRCW0402100KFKEDC_0402-IPC_B]  (hidden comment: CRCW0402100KFKEDC)
R238  Res_ohm: 100k  [FP-CRCW0402100KFKEDC_0402-IPC_B]  (hidden comment: CRCW0402100KFKEDC)
R244  Res_ohm: 100k  [FP-CRCW0402100KFKEDC_0402-IPC_B]  (hidden comment: CRCW0402100KFKEDC)
TP9  TESTPOINT  [TP_25MIL-SMT]  (value not drawn)  (no BOM)
TP11  TESTPOINT  [TP_VIA_060RND040]  (value not drawn)  (no BOM)
U18  TPS6285021HQDRLRQ1  [DRL0008A-MFG]
U19  TPS628502QDRLRQ1  [DRL0008A-MFG]
U20  TPS6285020MQDRLRQ1  [DRL0008A-MFG]

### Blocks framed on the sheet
DC-DC REGULATORS - 3.3V, 1.2V & 1.8V OUTPUTS: C54 C56 C60-C62 C66-C74 C79 C87 C100 C107 C119-C122 C128-C131 L1 L4-L6 L13-L15 R43 R119 R121 R178 R180 R232 R238 R244 U18-U20
The 3V3 Output from DC Regulator is used as PGOOD: L11 Q3 R173 R175-R177 R198 R201 TP9 TP11

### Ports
PGOOD (out), RADAR_NRST (out), REG_MODE_SELECT

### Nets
5V_IN: C56.1 C60.1 C62.1 C66.1 C67.1 C69.1 C72.1 C73.1 C74.1 R232.1 R238.1 R244.1 U18.1(VIN) U18.2(EN) U19.1(VIN) U19.2(EN) U20.1(VIN) U20.2(EN)
GND: C54.1 C56.2 C60.2 C61.1 C62.2 C66.2 C67.2 C68.1 C69.2 C70.2 C71.2 C72.2 C73.2 C74.2 C79.1 C87.1 C107.1 C119.2 C120.2 C121.1 C122.1 C128.2 C129.2 C130.1 C131.1 Q3.2(S) R43.1 R121.1 R177.1 R178.1 R180.1 R201.1 TP11.1 U18.8(GND) U19.8(GND) U20.8(GND)
REG_1V2: C61.2 L5.2
REG_1V8: C68.2 L6.2
REG_3V3: C54.2 L4.2 L11.1 R175.2
REG_OUT_1V2: C100.1 C119.1 C120.1 C121.2 C122.2 L1.1 L5.1 L14.2 R119.2
REG_OUT_1V8: C128.1 C129.1 C130.2 C131.2 L6.1 L15.2 U20.5(FB)
REG_OUT_3V3: C70.1 C71.1 C87.2 C107.2 L4.1 L13.2 U18.5(FB)
REG_RF_1V2: C79.2 L1.2
VCC_3V3: L11.2 R198.2 TP9.1
COMP1: R43.2 U18.4(COMP/FSET)
COMP2: R178.2 U19.4(COMP/FSET)
COMP3: R180.2 U20.4(COMP/FSET)
MODE: Q3.3(D) R232.2 R238.2 R244.2 U18.3(MODE) U19.3(MODE) U20.3(MODE/SYNC)
PGOOD: R198.1 R201.2 ; port PGOOD
RADAR_NRST: R176.1 ; port RADAR_NRST
REG_MODE_SELECT: R173.2 ; port REG_MODE_SELECT
REG_PG: R175.1 R176.2 U18.6(PG) U19.6(PG) U20.6(PG)
SW1: L13.1 U18.7(SW)
SW2: L14.1 U19.7(SW)
SW3: L15.1 U20.7(SW)
NetC100_2: C100.2 R119.1 R121.2 U19.5(FB)
NetQ3_1: Q3.1(G) R173.1 R177.2

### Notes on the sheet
- CAD NOTE : Place all Input & Output Decaps close to Regulator Pins - U[18:20]

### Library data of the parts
C54 C61 C79 C87 C107 C121 C122 C130 C131 = CMP-0092150-1: Chip Multilayer Ceramic Capacitors for General Purpose, 1206, 22uF, X7R, 15%, 20%, 6.3V; Manufacturer: Murata; SizeZ_mm: 1.8mm; AEC Qualified: No; Value: 22µF
C56 C62 C72 = CMP-0007497-5: CAP, CERM, 10 uF, 10 V, +/- 20%, X7R, 0603; Manufacturer: MuRata; TaMin_C: -55°C; Polarized: N; SizeAreaWB_mm2: 4.68; Value1: Unknown; U/M: EA; Value: 10uF; TaMax_C: 125°C; SizeZ_mm: 1; SizeX_mm: 1.6; SizeY_mm: 0.8; Cap_Case: 0603; SizeArea_mm2: 1.28; AEC Category: Q200
C60 C66 C73 = CMP-0007398-4: CAP, CERM, 0.47 uF, 16 V, +/- 10%, X7R, 0603; Manufacturer: MuRata; TaMin_C: -55°C; Polarized: N; SizeAreaWB_mm2: 4.68; Value1: Unknown; U/M: EA; Value: 0.47uF; TaMax_C: 125°C; SizeZ_mm: 1; SizeX_mm: 1.6; SizeY_mm: 0.8; Cap_Case: 0603; Value2: 16V; SizeArea_mm2: 1.28; AEC Category: Q200
C67 C69 C74 = CMP-0006470-2: CAP, CERM, 470 pF, 50 V, +/- 5%, C0G/NP0, 0402; Manufacturer: MuRata; TaMin_C: -55°C; Polarized: N; SizeAreaWB_mm2: 3; Value1: Unknown; U/M: EA; Value: 470pF; TaMax_C: 125°C; SizeZ_mm: 0.6; SizeX_mm: 1; SizeY_mm: 0.5; Cap_Case: 0402; Value2: 50V; AEC Category: Q200
C68 = CMP-0008940-2: CAP, CERM, 47 uF, 6.3 V, +/- 20%, X5R, 1206; Manufacturer: MuRata; TaMin_C: -55°C; ESR_ohm: 3m; Polarized: N; SizeAreaWB_mm2: 10.92; Value1: 0.003 ohm; U/M: EA; Value: 47uF; TaMax_C: 85°C; SizeZ_mm: 1.8; SizeX_mm: 3.2; SizeY_mm: 1.6; Cap_Case: 1206; Value2: 6.3V; SizeArea_mm2: 5.12; Cap_F: 47µF; AEC Category: Q200
C70 C71 C119 C120 C128 C129 = CMP-0007497-5: as C135 on sheet PROC117B_USB_PWR_DC_Jack_Switch
C100 = CMP-0006307-2: CAP, CERM, 10 pF, 50 V, +/- 5%, C0G/NP0, AEC-Q200 Grade 1, 0402; Manufacturer: TDK; TaMin_C: -55°C; Polarized: N; SizeAreaWB_mm2: 3; Value1: Unknown; U/M: EA; Value: 10pF; TaMax_C: 125°C; SizeZ_mm: 0.6; SizeX_mm: 1; SizeY_mm: 0.5; Value2: 50V; AEC Qualified: Y; AEC Category: Q200
L1 L4-L6 = CMP-0095018-1: 100nH Shielded Multilayer Inductor 4A 19mOhm Max 0806 (2016 Metric); Manufacturer: Murata; Tolerance_%: 20%; Self Resonant Frequency: 200MHz; Test Frequency: 1MHz; Irms: 4000mA; Shrouded: true; SizeZ_mm: 1.2mm; Value: 0.1uH; AEC Grade: Grade 1; DCR_ohm: 0.019; Material: Ferrite; AEC Qualified: Yes
L11 = CMP-0078934-1: as L9 on sheet PROC117B_USB_PWR_DC_Jack_Switch
L13-L15 = CMP-0092096-1: 470nH Shielded Wirewound Inductor 3A 42mOhm Max 0805 (2012 Metric); Manufacturer: Murata; DCR_ohm: 0.042; Shrouded: true; SizeZ_mm: 1mm; Value: 0.47uH; Tolerance_%: 20%; Test Frequency: 1MHz; Isat: 4.4A; AEC Qualified: No; Material: Metal Alloy
Q3 = CMP-0000948-2: as Q2 on sheet PROC117B_USB_PWR_DC_Jack_Switch
R43 R178 R180 = CMP-0026058-3: RES, 18.0 k, 1%, 0.063 W, AEC-Q200 Grade 0, 0402; Manufacturer: Vishay-Dale; Power_W: 63mW; TempCo: 100 ppm/C; Value_Code: 18k0; Value: 18.0k; Res_ohm: 18k; SizeX_mm: 1; SizeY_mm: 0.5; SizeZ_mm: 0.6; Value2: 0.063W; AEC Qualified: Y; VDC_V: 50V; AEC Grade: 0; AEC Category: Q200
R119 R121 = CMP-0095242-1: 68kΩ ±1% 0.063W 0402 Thick Film Chip Resistor AEC-Q200 compliant; Manufacturer: Stackpole Electronics; AEC Qualified: Yes; TempCo: 100ppm/°C; Power_W: 63mW; Value: 68k; AEC Grade: Grade 0; VDC_V: 50V; SizeZ_mm: 0.35mm
R173 R176 R198 = CMP-0086442-2: RES SMD 0 OHM JUMPER 1/20W 0201; Manufacturer: Yageo; AEC Qualified: No; Power_W: 50mW; SizeZ_mm: 0.26mm; TempCo: 200ppm/°C; Tolerance_%: 5%; VDC_V: 25V
R175 R177 R232 R238 R244 = CMP-0092204-1: 100 kOhms ±1% 0.063W, 1/16W Chip Resistor 0402 (1005 Metric)  Thick Film; Manufacturer: Vishay; Power_W: 63mW; AEC Qualified: No; TempCo: 100ppm/°C; SizeZ_mm: 0.35mm; VDC_V: 50V; Value: 100k
R201 = CMP-0027261-3: as R120 on sheet PROC117B_USB_PWR_DC_Jack_Switch
TP9 TP11 = CMP-0078143-3: TEST POINT.  No entry in BOM.
U18 = CMP-0092337-2: 2.7-V to 6-V, 2-A Automotive Step-Down Converter in SOT583 Package; Manufacturer: Texas Instruments; TaMax_C: +125°C; Switching Topology: Buck; Max Duty Cycle: 100%; Min Supply Voltage: 2.7V; TJmax_C: +150°C; Number Of Outputs: 1; Switching Frequency: 1.8-4MHz; TaMin_C: -40°C; Max Supply Voltage: 6V; SizeZ_mm: 0.6mm; Nominal Supply Current: 17uA; Standoff Height: 0mm; AEC Qualified: Yes; Output Voltage: 0.6-5.5V; Output Type: AdjustableProgrammable; AEC Grade: Grade 1; AEC Category: Q200; CompType: IC
U19 = CMP-0088303-1: 2.7-V to 6-V Adjustable-Frequency Step-Down Converter in SOT583 Package; Manufacturer: Texas Instruments; TaMin_C: -40°C; Standoff Height: 0mm; Switching Topology: Buck; Nominal Supply Current: 15uA; Min Supply Voltage: 2.7V; TaMax_C: +125°C; Switching Frequency: 1.8-3.5MHz; Max Supply Voltage: 6V; SizeZ_mm: 0.6mm; Number Of Outputs: 1; Max Duty Cycle: 100%; AEC Qualified: Yes; AEC Grade: Grade 1; Output Voltage: 0.5-5.5V; Output Type: AdjustableProgrammable
U20 = CMP-0088311-1: 2.7-V to 6-V Adjustable-Frequency Step-Down Converter in SOT583 Package; Manufacturer: Texas Instruments; Number Of Outputs: 1; Max Supply Voltage: 6V; Max Duty Cycle: 100%; Min Supply Voltage: 2.7V; Switching Frequency: 1.8-3.5MHz; Nominal Supply Current: 15uA; SizeZ_mm: 0.6mm; Switching Topology: Buck; AEC Grade: Grade 1; TJmax_C: +150°C; TaMin_C: -40°C; Standoff Height: 0mm; Output Type: Fixed; Output Voltage: 1.8V; AEC Qualified: Yes; TaMax_C: +125°C

## Sheet PROC117B_xWRL6432_Chip.SchDoc: xWRL6432_CHIP
size 431 x 279 mm; Date: Not shown in title block; ApprovedBy: Not shown in title block; CheckedBy: Not shown in title block; Author: Not shown in title block; CompanyName: Not shown in title block; DrawnBy: Mistral; Engineer: Not shown in title block; Organization: Not shown in title block; Address1: Not shown in title block; Address2: Not shown in title block; Address3: Not shown in title block; Address4: Not shown in title block; DocumentNumber: 6; Revision: Use project parameter SCH_Rev; SheetNumber: 6; SheetTotal: 16; PageSetup: Record=PageOptions¦CenterHorizontal=True¦CenterVertical=True¦PrintScale=1.00¦XCorrection=1.00¦YCorrection=1.00¦PrintKind=0¦BorderSize=5000000¦LeftOffset=0¦BottomOffset=0¦Orientation=2¦PaperLength=1000¦PaperWidth=1000¦Scale=100¦PaperSource=15¦PrintQuality=600¦MediaType=1¦DitherType=10¦PaperKind=Letter¦PrintScaleMode=1
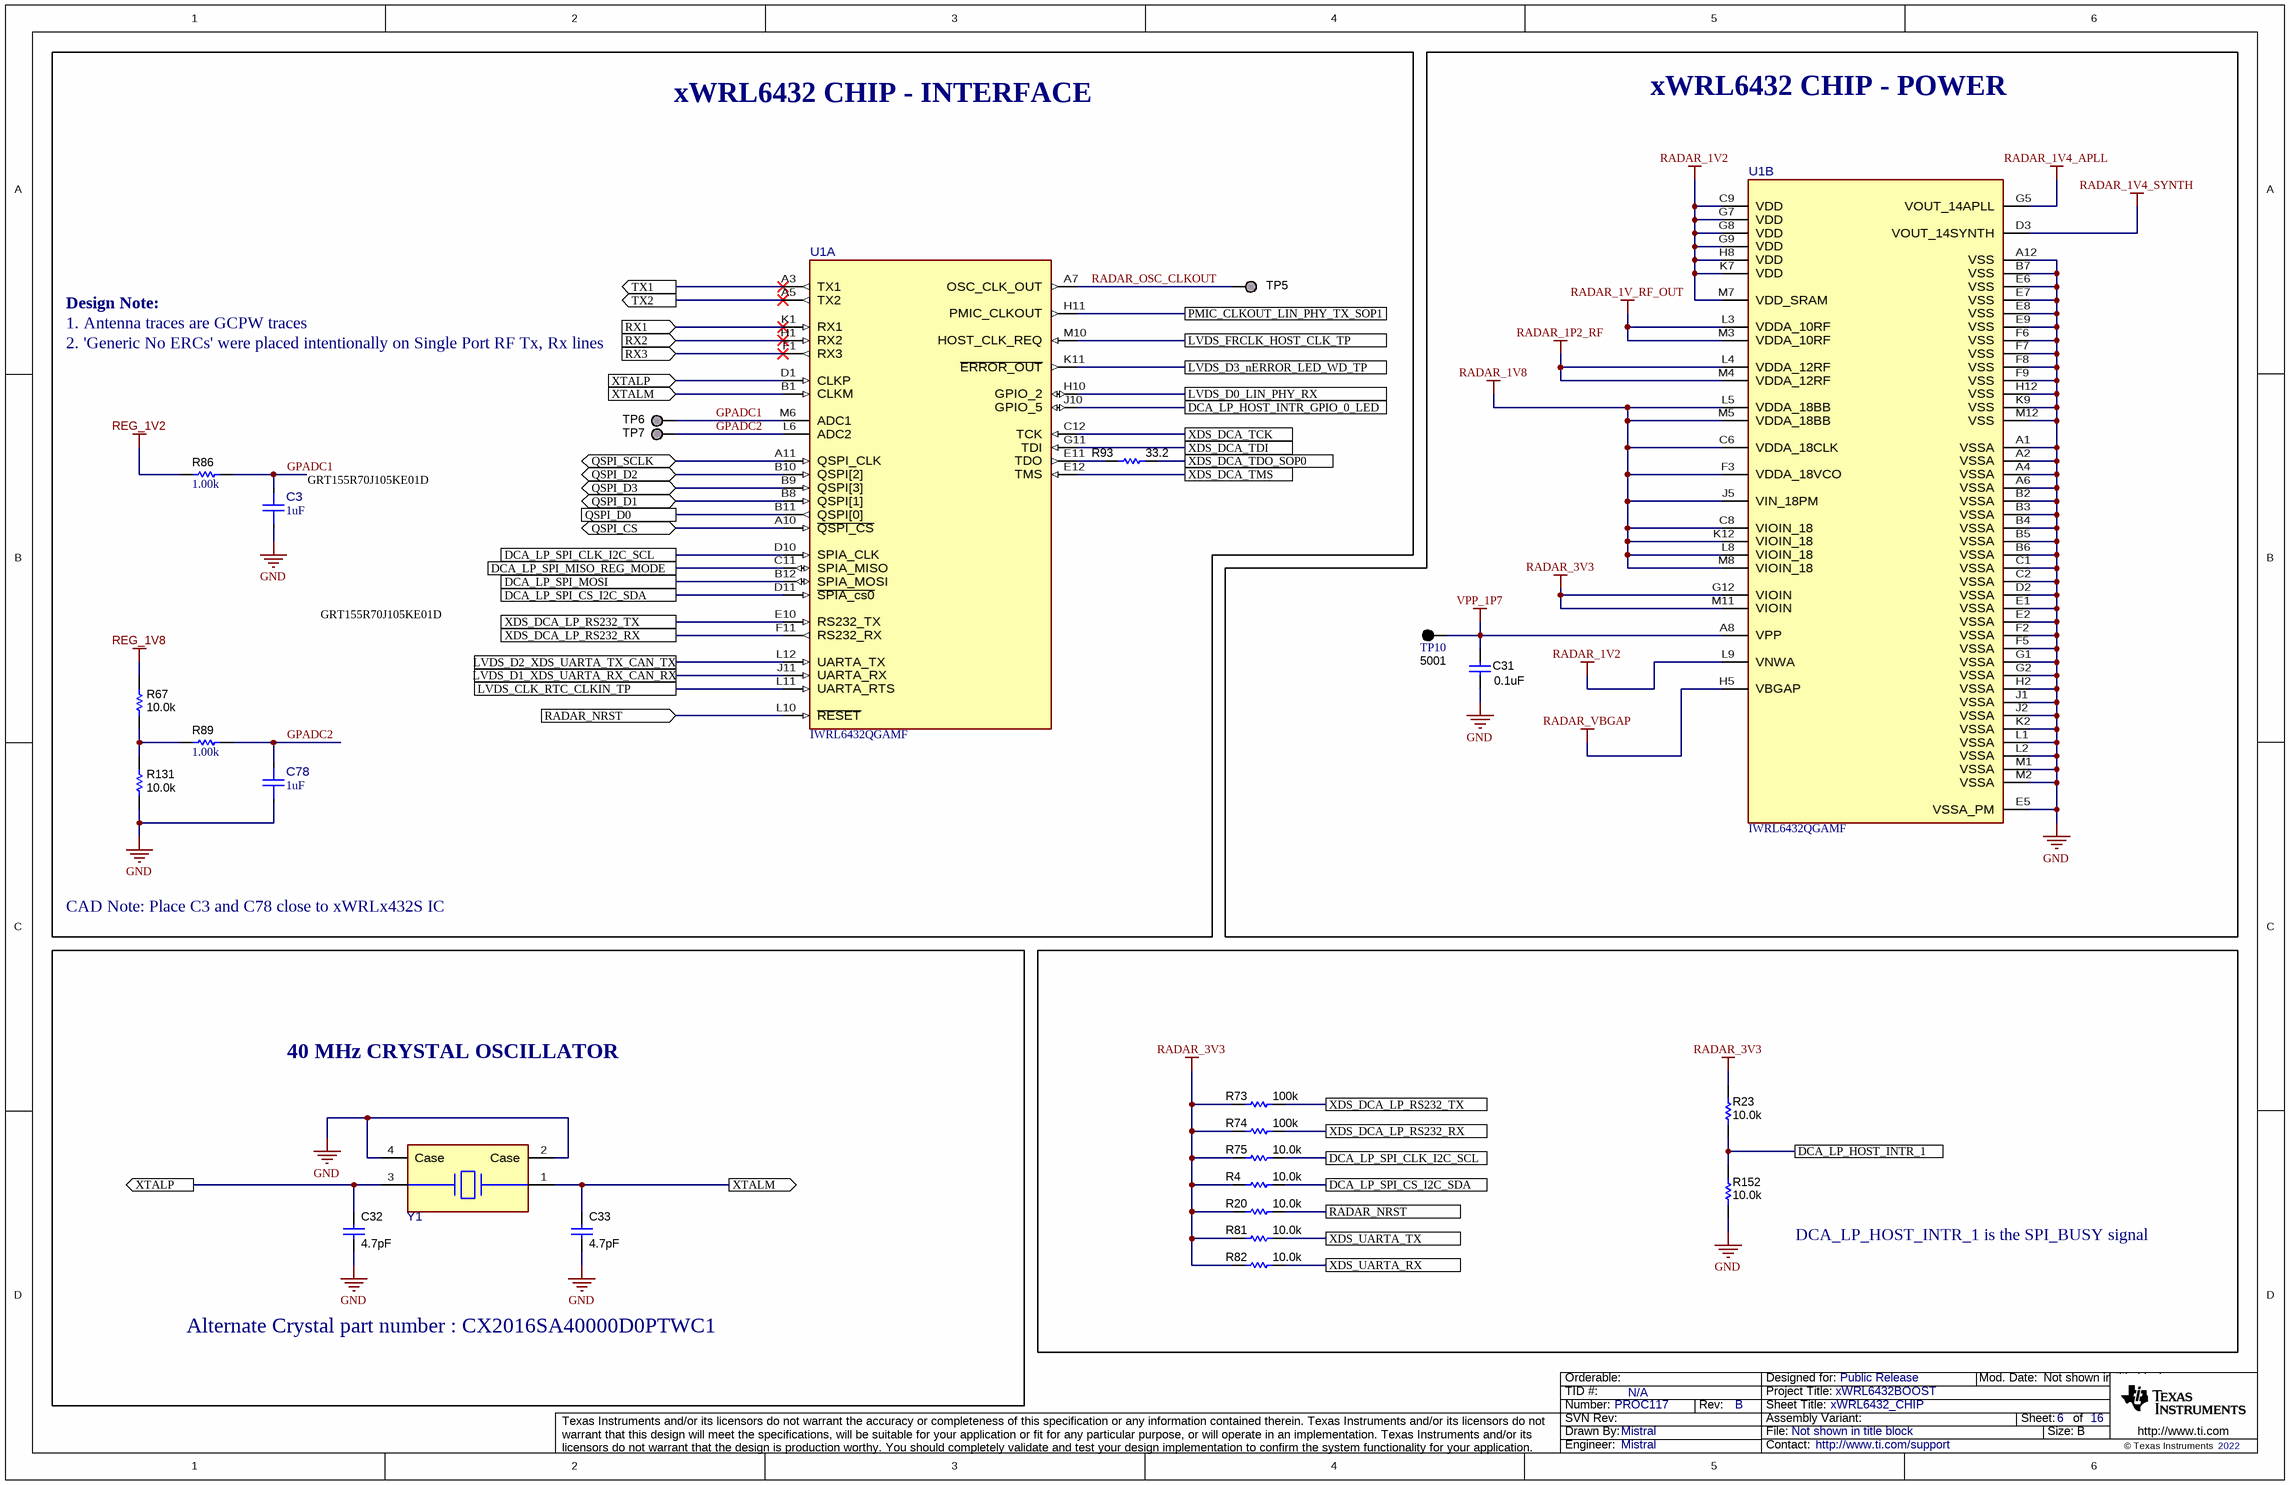
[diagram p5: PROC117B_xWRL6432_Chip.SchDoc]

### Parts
C3  ValueDisplayed: 1uF  [FP-GRT155R70J105KE01D_0402-MFG]  (hidden comment: GRT155R70J105KE01D)
C31  ValueDisplayed: 0.1uF  [0201]  (hidden comment: GRM033C71A104KE14D)
C32  ValueDisplayed: 4.7pF  [0402L]  (hidden comment: GJM1555C1H4R7BB01D)
C33  ValueDisplayed: 4.7pF  [0402L]  (hidden comment: GJM1555C1H4R7BB01D)
C78  ValueDisplayed: 1uF  [FP-GRT155R70J105KE01D_0402-MFG]  (hidden comment: GRT155R70J105KE01D)
R4  ValueDisplayed: 10.0k  [0402L]  (hidden comment: CRCW040210K0FKED)
R20  ValueDisplayed: 10.0k  [0402L]  (hidden comment: CRCW040210K0FKED)
R23  ValueDisplayed: 10.0k  [0402L]  (hidden comment: CRCW040210K0FKED)
R67  ValueDisplayed: 10.0k  [0402L]  (hidden comment: CRCW040210K0FKED)
R73  ValueDisplayed: 100k  [0402L]  (hidden comment: CRCW0402100KFKED)
R74  ValueDisplayed: 100k  [0402L]  (hidden comment: CRCW0402100KFKED)
R75  ValueDisplayed: 10.0k  [0402L]  (hidden comment: CRCW040210K0FKED)
R81  ValueDisplayed: 10.0k  [0402L]  (hidden comment: CRCW040210K0FKED)
R82  ValueDisplayed: 10.0k  [0402L]  (hidden comment: CRCW040210K0FKED)
R86  ValueDisplayed: 1.00k  [0402L]  (hidden comment: CRCW04021K00FKED)
R89  ValueDisplayed: 1.00k  [0402L]  (hidden comment: CRCW04021K00FKED)
R93  ValueDisplayed: 33.2  [0201_Silk]  (hidden comment: CRCW020133R2FNED)
R131  ValueDisplayed: 10.0k  [0402L]  (hidden comment: CRCW040210K0FKED)
R152  ValueDisplayed: 10.0k  [0402L]  (hidden comment: CRCW040210K0FKED)
TP5  TESTPOINT  [TP_25MIL-SMT]  (value not drawn)  (no BOM)
TP6  TESTPOINT  [TP_25MIL-SMT]  (value not drawn)  (no BOM)
TP7  TESTPOINT  [TP_25MIL-SMT]  (value not drawn)  (no BOM)
TP10  5001  [Keystone5001]
U1  IWRL6432QGAMF  [AMF0102A-MFG]  (parts A,B of 2)
Y1  FW4000044Q  [FP-FW4000044Q_4-SMD-2.0x1.6mm-MFG]  (value not drawn)

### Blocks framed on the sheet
xWRL6432 CHIP - INTERFACE: C3 C78 R67 R86 R89 R93 R131 TP5-TP7 U1
xWRL6432 CHIP - POWER: C31 TP10 U1
DCA_LP_HOST_INTR_1 is the SPI_BUSY signal: R4 R20 R23 R73-R75 R81 R82 R152

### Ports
DCA_LP_HOST_INTR_1, DCA_LP_HOST_INTR_GPIO_0_LED, DCA_LP_SPI_CLK_I2C_SCL, DCA_LP_SPI_CS_I2C_SDA, DCA_LP_SPI_MISO_REG_MODE, DCA_LP_SPI_MOSI, LVDS_CLK_RTC_CLKIN_TP, LVDS_D0_LIN_PHY_RX, LVDS_D1_XDS_UARTA_RX_CAN_RX, LVDS_D2_XDS_UARTA_TX_CAN_TX, LVDS_D3_nERROR_LED_WD_TP, LVDS_FRCLK_HOST_CLK_TP, PMIC_CLKOUT_LIN_PHY_TX_SOP1, QSPI_CS (bidir), QSPI_D0, QSPI_D1 (bidir), QSPI_D2 (bidir), QSPI_D3 (bidir), QSPI_SCLK (bidir), RADAR_NRST, RADAR_NRST (in), RX1 (in), RX2 (in), RX3 (in), TX1 (out), TX2 (out), XDS_DCA_LP_RS232_RX, XDS_DCA_LP_RS232_TX, XDS_DCA_TCK, XDS_DCA_TDI, XDS_DCA_TDO_SOP0, XDS_DCA_TMS, XDS_UARTA_RX, XDS_UARTA_TX, XTALM (in), XTALM (out), XTALP (in), XTALP (out)

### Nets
GND: C3.1 C31.1 C32.1 C33.1 C78.1 R131.1 R152.2 U1.A1(VSSA) U1.A2(VSSA) U1.A4(VSSA) U1.A6(VSSA) U1.A12(VSS) U1.B2(VSSA) U1.B3(VSSA) U1.B4(VSSA) U1.B5(VSSA) U1.B6(VSSA) U1.B7(VSS) U1.C1(VSSA) U1.C2(VSSA) U1.D2(VSSA) U1.E1(VSSA) U1.E2(VSSA) U1.E5(VSSA_PM) U1.E6(VSS) U1.E7(VSS) U1.E8(VSS) U1.E9(VSS) U1.F2(VSSA) U1.F5(VSSA) U1.F6(VSS) U1.F7(VSS) U1.F8(VSS) U1.F9(VSS) U1.G1(VSSA) U1.G2(VSSA) U1.H2(VSSA) U1.H12(VSS) U1.J1(VSSA) U1.J2(VSSA) U1.K2(VSSA) U1.K9(VSS) U1.L1(VSSA) U1.L2(VSSA) U1.M1(VSSA) U1.M2(VSSA) U1.M12(VSS) Y1.2(Case) Y1.4(Case)
RADAR_1P2_RF: U1.L4(VDDA_12RF) U1.M4(VDDA_12RF)
RADAR_1V2: U1.C9(VDD) U1.G7(VDD) U1.G8(VDD) U1.G9(VDD) U1.H8(VDD) U1.K7(VDD) U1.L9(VNWA) U1.M7(VDD_SRAM)
RADAR_1V4_APLL: U1.G5(VOUT_14APLL)
RADAR_1V4_SYNTH: U1.D3(VOUT_14SYNTH)
RADAR_1V8: U1.C6(VDDA_18CLK) U1.C8(VIOIN_18) U1.F3(VDDA_18VCO) U1.J5(VIN_18PM) U1.K12(VIOIN_18) U1.L5(VDDA_18BB) U1.L8(VIOIN_18) U1.M5(VDDA_18BB) U1.M8(VIOIN_18)
RADAR_1V_RF_OUT: U1.L3(VDDA_10RF) U1.M3(VDDA_10RF)
RADAR_3V3: R4.2 R20.2 R23.1 R73.2 R74.2 R75.2 R81.2 R82.2 U1.G12(VIOIN) U1.M11(VIOIN)
RADAR_VBGAP: U1.H5(VBGAP)
REG_1V2: R86.2
REG_1V8: R67.2
VPP_1P7: C31.2 TP10.1 U1.A8(VPP)
DCA_LP_HOST_INTR_1: R23.2 R152.1 ; port DCA_LP_HOST_INTR_1
DCA_LP_HOST_INTR_GPIO_0_LED: U1.J10(GPIO_5) ; port DCA_LP_HOST_INTR_GPIO_0_LED
DCA_LP_SPI_CLK_I2C_SCL: R75.1 U1.D10(SPIA_CLK) ; port DCA_LP_SPI_CLK_I2C_SCL
DCA_LP_SPI_CS_I2C_SDA: R4.1 U1.D11(~{SPIA_cs0}) ; port DCA_LP_SPI_CS_I2C_SDA
DCA_LP_SPI_MISO_REG_MODE: U1.C11(SPIA_MISO) ; port DCA_LP_SPI_MISO_REG_MODE
DCA_LP_SPI_MOSI: U1.B12(SPIA_MOSI) ; port DCA_LP_SPI_MOSI
GPADC1: C3.2 R86.1 TP6.1 U1.M6(ADC1)
GPADC2: C78.2 R89.1 TP7.1 U1.L6(ADC2)
LVDS_CLK_RTC_CLKIN_TP: U1.L11(UARTA_RTS) ; port LVDS_CLK_RTC_CLKIN_TP
LVDS_D0_LIN_PHY_RX: U1.H10(GPIO_2) ; port LVDS_D0_LIN_PHY_RX
LVDS_D1_XDS_UARTA_RX_CAN_RX: U1.J11(UARTA_RX) ; port LVDS_D1_XDS_UARTA_RX_CAN_RX
LVDS_D2_XDS_UARTA_TX_CAN_TX: U1.L12(UARTA_TX) ; port LVDS_D2_XDS_UARTA_TX_CAN_TX
LVDS_D3_nERROR_LED_WD_TP: U1.K11(~{ERROR_OUT}) ; port LVDS_D3_nERROR_LED_WD_TP
LVDS_FRCLK_HOST_CLK_TP: U1.M10(HOST_CLK_REQ) ; port LVDS_FRCLK_HOST_CLK_TP
PMIC_CLKOUT_LIN_PHY_TX_SOP1: U1.H11(PMIC_CLKOUT) ; port PMIC_CLKOUT_LIN_PHY_TX_SOP1
QSPI_CS: U1.A10(~{QSPI_CS}) ; port QSPI_CS
QSPI_D0: U1.B11(QSPI[0]) ; port QSPI_D0
QSPI_D1: U1.B8(QSPI[1]) ; port QSPI_D1
QSPI_D2: U1.B10(QSPI[2]) ; port QSPI_D2
QSPI_D3: U1.B9(QSPI[3]) ; port QSPI_D3
QSPI_SCLK: U1.A11(QSPI_CLK) ; port QSPI_SCLK
RADAR_NRST: R20.1 U1.L10(~{RESET}) ; port RADAR_NRST
RADAR_OSC_CLKOUT: TP5.1 U1.A7(OSC_CLK_OUT)
RX1: U1.K1(RX1) ; port RX1
RX2: U1.H1(RX2) ; port RX2
RX3: U1.F1(RX3) ; port RX3
TX1: U1.A3(TX1) ; port TX1
TX2: U1.A5(TX2) ; port TX2
XDS_DCA_LP_RS232_RX: R74.1 U1.F11(RS232_RX) ; port XDS_DCA_LP_RS232_RX
XDS_DCA_LP_RS232_TX: R73.1 U1.E10(RS232_TX) ; port XDS_DCA_LP_RS232_TX
XDS_DCA_TCK: U1.C12(TCK) ; port XDS_DCA_TCK
XDS_DCA_TDI: U1.G11(TDI) ; port XDS_DCA_TDI
XDS_DCA_TDO_SOP0: R93.1 ; port XDS_DCA_TDO_SOP0
XDS_DCA_TMS: U1.E12(TMS) ; port XDS_DCA_TMS
XDS_UARTA_RX: R82.1 ; port XDS_UARTA_RX
XDS_UARTA_TX: R81.1 ; port XDS_UARTA_TX
XTALM: C33.2 U1.B1(CLKM) Y1.1(1_Xtal) ; port XTALM
XTALP: C32.2 U1.D1(CLKP) Y1.3(2_Xtal) ; port XTALP
NetR67_1: R67.1 R89.2 R131.2
NetR93_2: R93.2 U1.E11(TDO)

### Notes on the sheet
- 1. Antenna traces are GCPW traces
- 2. 'Generic No ERCs' were placed intentionally on Single Port RF Tx, Rx lines
- Design Note:
- (near C3) GRT155R70J105KE01D
- GRT155R70J105KE01D
- CAD Note: Place C3 and C78 close to xWRLx432S IC
- 40 MHz CRYSTAL OSCILLATOR
- Alternate Crystal part number : CX2016SA40000D0PTWC1

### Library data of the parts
C3 C78 = CMP-0088425-1: 1µF ±10% 6.3V Ceramic Capacitor X7R 0402 (1005 Metric); Manufacturer: Murata; AEC Grade: Grade 1; SizeZ_mm: 0.55mm; AEC Qualified: Yes; TempCo: 15%
C31 = CMP-0064969-1: CAP, CERM, 0.1 uF, 10 V,+/- 10%, X7S, 0201; Manufacturer: MuRata; TaMin_C: -55°C; Polarized: N; SizeAreaWB_mm2: 2.08; Value1: Unknown; U/M: EA; Value: 0.1uF; TaMax_C: 125°C; SizeZ_mm: 0.26; SizeX_mm: 0.6; SizeY_mm: 0.3; Value2: 10V; SizeArea_mm2: 0.18; Cap_F: 100nF; AEC Category: Q200
C32 C33 = CMP-0006367-2: CAP, CERM, 4.7 pF, 50 V, +/- 2%, C0G/NP0, 0402; Manufacturer: MuRata; TaMin_C: -55°C; Polarized: N; SizeAreaWB_mm2: 3; Value1: Unknown; U/M: EA; Value: 4.7pF; TaMax_C: 125°C; SizeZ_mm: 0.6; SizeX_mm: 1; SizeY_mm: 0.5; Cap_Case: 0402; Value2: 50V; CompType: Capacitor; AEC Category: Q200
R4 R20 R23 R67 R75 R81 R82 R131 R152 = CMP-0025958-3: as R72 on sheet PROC117B_USB_PWR_DC_Jack_Switch
R73 R74 = CMP-0025950-3: RES, 100 k, 1%, 0.063 W, AEC-Q200 Grade 0, 0402; Manufacturer: Vishay-Dale; Power_W: 63mW; TempCo: 100 ppm/C; Value: 100k; EIA_Code: E96; SizeX_mm: 1; SizeY_mm: 0.5; SizeZ_mm: 0.6; Value2: 0.063W; AEC Qualified: Y; VDC_V: 50V; AEC Category: Q200; AEC Grade: 0
R86 R89 = CMP-0026071-3: RES, 1.00 k, 1%, 0.063 W, AEC-Q200 Grade 0, 0402; Manufacturer: Vishay-Dale; Power_W: 63mW; TempCo: 100 ppm/C; Value_Code: 1k00; Value: 1.00k; EIA_Code: E96; Res_ohm: 1k; SizeX_mm: 1; SizeY_mm: 0.5; SizeZ_mm: 0.6; Value2: 0.063W; AEC Qualified: Y; VDC_V: 50V; AEC Category: Q200; AEC Grade: 0
R93 = CMP-0027275-3: RES, 33.2, 1%, 0.05 W, 0201; Manufacturer: Vishay-Dale; Power_W: 50mW; TempCo: 200 ppm/C; Value_Code: 33R2; Value: 33.2; EIA_Code: E96; SizeX_mm: 0.6; SizeY_mm: 0.3; SizeZ_mm: 0.26; Value2: 0.05W; SizeArea_mm2: 0.18; AEC Qualified: N; AEC Category: Q200
TP5-TP7 = CMP-0078143-3: TEST POINT.  No entry in BOM.
TP10 = CMP-0055138-2: Test Point, Miniature, Black, TH; Manufacturer: Keystone Electronics; ContactFinish: Silver; CNHeader: FALSE; Green_Lifecycle: Active; Green_REACh: Passed; CT: TRUE
U1 = CMP-0095272-2: Manufacturer: Texas Instruments; SizeZ_mm: 0.97mm; Standoff Height: 0.15mm; CompType: IC; AEC Category: Q200
Y1 = CMP-0090505-1: 40MHz ±10ppm Crystal 8pF 50 Ohms 4-SMD, No Lead; Manufacturer: Diodes; Alternate Part Number: CX2016SA40000D0PTWC1; Frequency Stability: 50ppm; Esr: 50; AEC Qualified: Yes; AEC Grade: Grade 1; SizeZ_mm: 0.55mm

## Sheet PROC117B_Decoupling_caps.SchDoc: DECOUPLING_CAPS
size 431 x 279 mm; Date: Not shown in title block; ApprovedBy: Not shown in title block; CheckedBy: Not shown in title block; Author: Not shown in title block; CompanyName: Not shown in title block; DrawnBy: Mistral; Engineer: Not shown in title block; Organization: Not shown in title block; Address1: Not shown in title block; Address2: Not shown in title block; Address3: Not shown in title block; Address4: Not shown in title block; DocumentNumber: 7; Revision: Use project parameter SCH_Rev; SheetNumber: 7; SheetTotal: 16; PageSetup: Record=PageOptions¦CenterHorizontal=True¦CenterVertical=True¦PrintScale=1.00¦XCorrection=1.00¦YCorrection=1.00¦PrintKind=0¦BorderSize=5000000¦LeftOffset=0¦BottomOffset=0¦Orientation=2¦PaperLength=1000¦PaperWidth=1000¦Scale=100¦PaperSource=15¦PrintQuality=600¦MediaType=1¦DitherType=10¦PaperKind=Letter¦PrintScaleMode=1
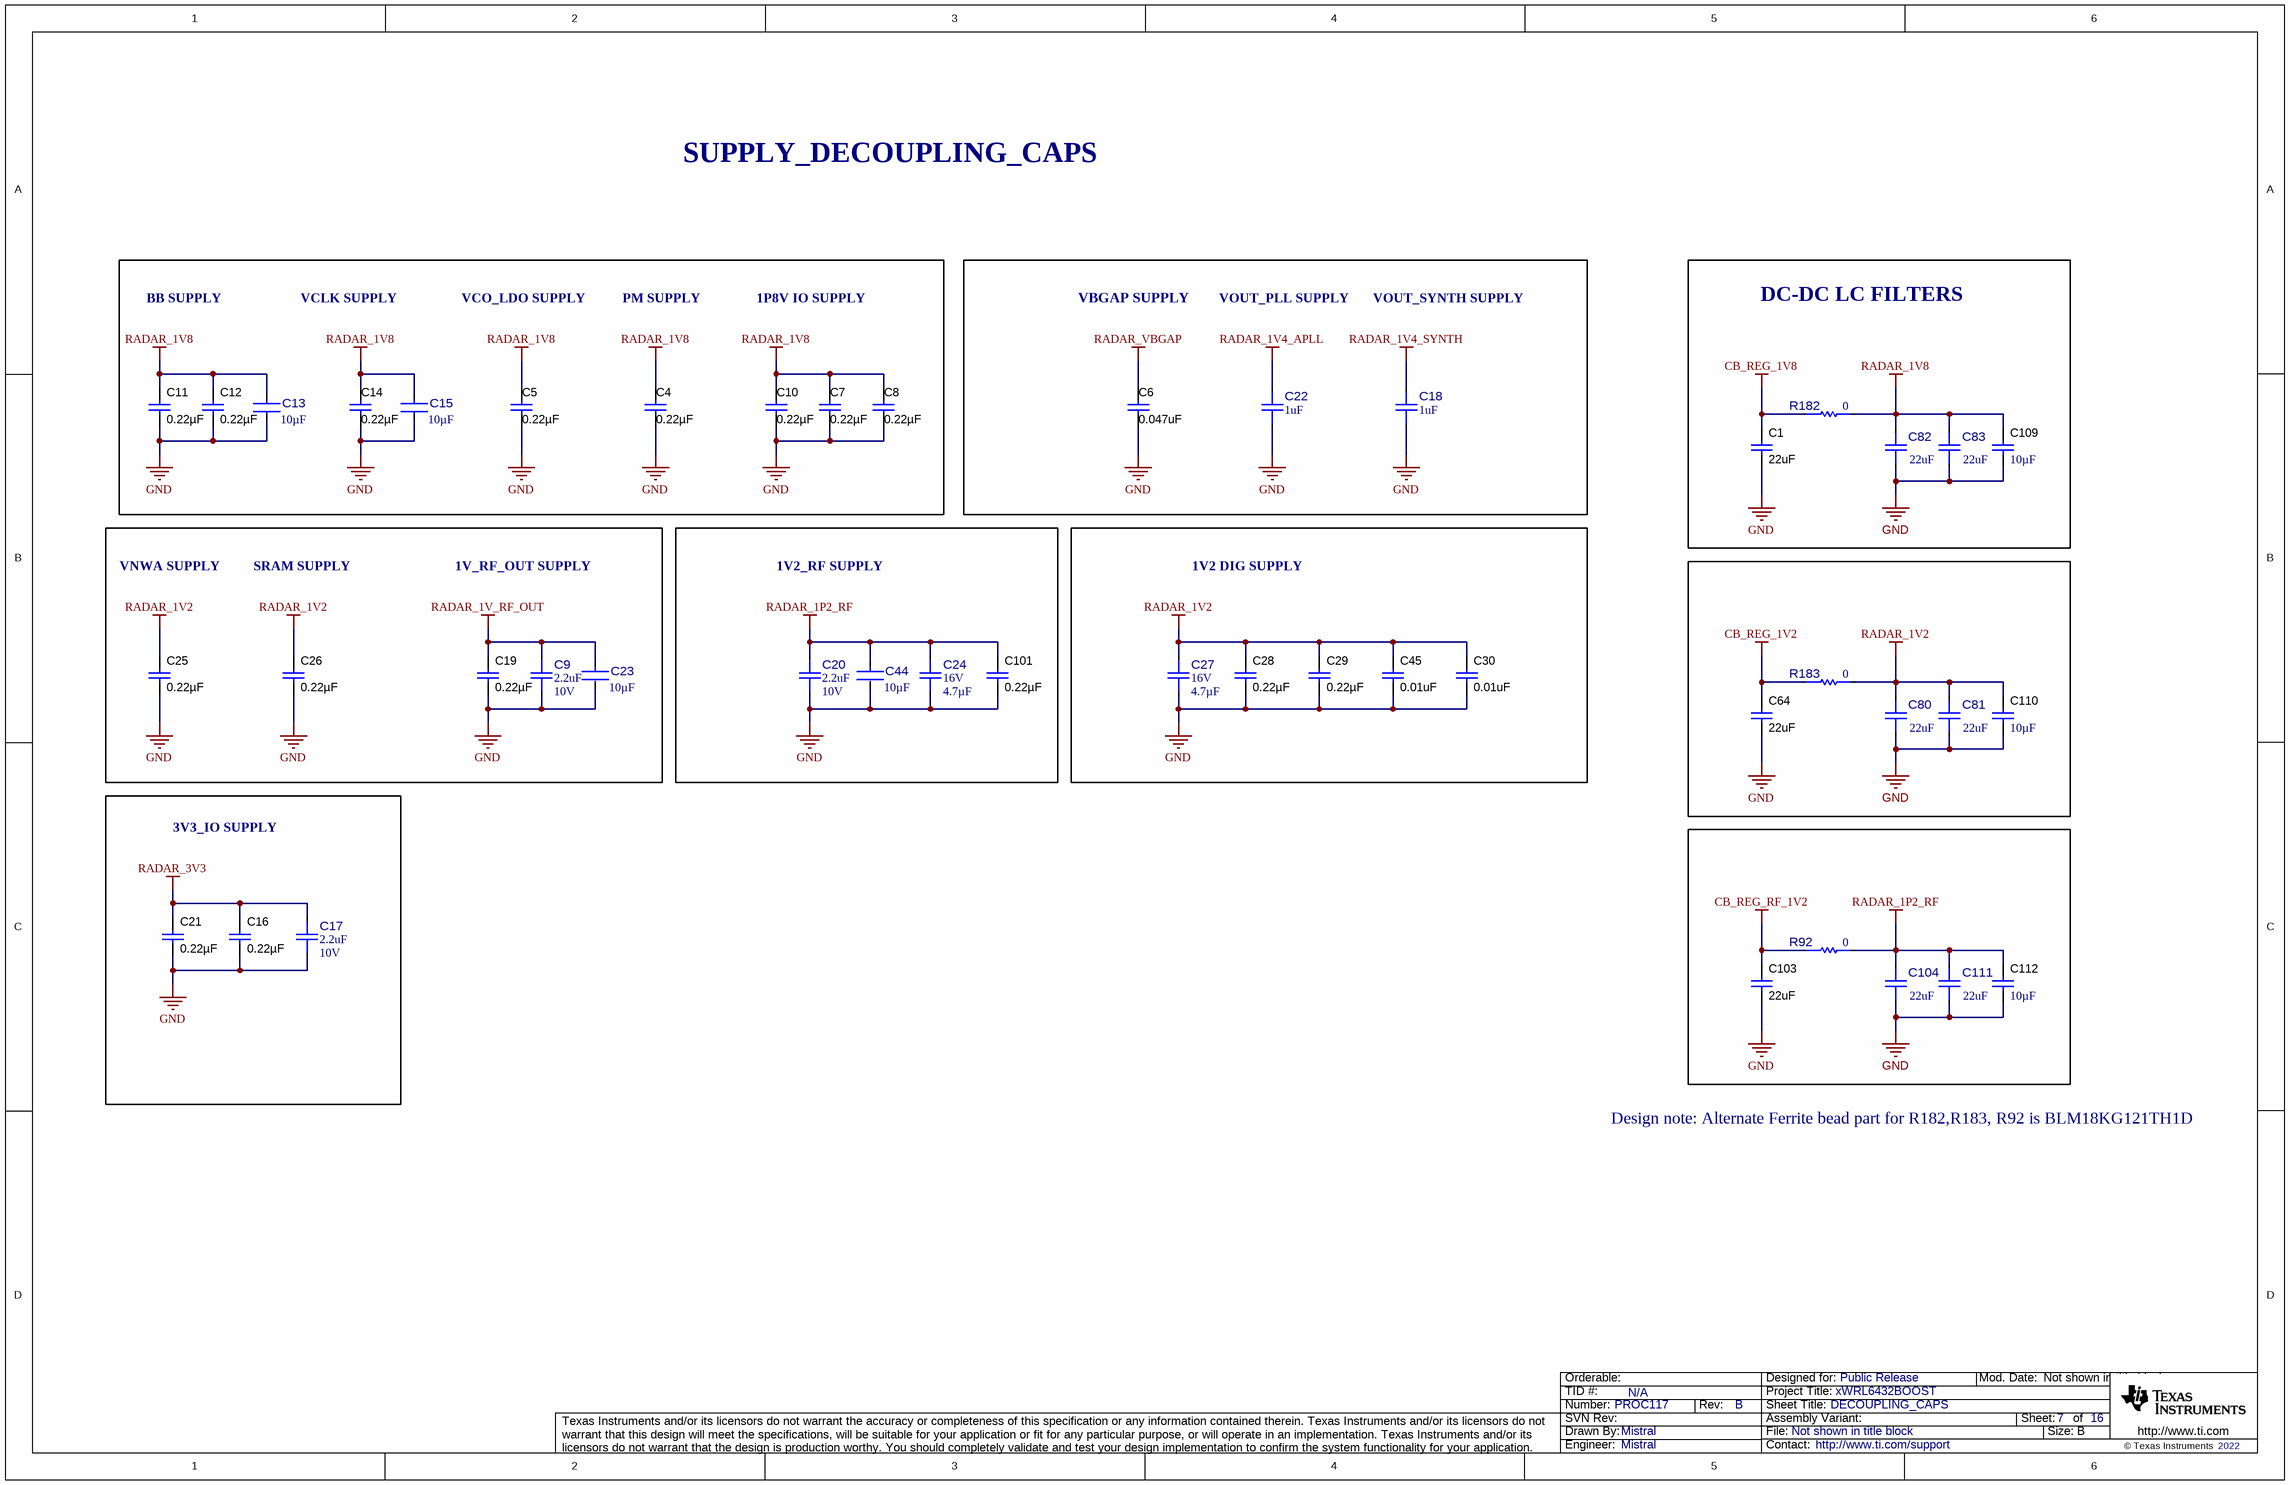
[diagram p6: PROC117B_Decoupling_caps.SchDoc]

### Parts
C1  ValueDisplayed: 22uF  [1206_180]  (hidden comment: CGA5L1X7R0J226M160AC)
C4  ValueDisplayed: 0.22µF  [0402L]  (hidden comment: GCM155R71C224KE02D)
C5  ValueDisplayed: 0.22µF  [0402L]  (hidden comment: GCM155R71C224KE02D)
C6  ValueDisplayed: 0.047uF  [0402L]  (hidden comment: CGA2B3X7R1H473K050BB)
C7  ValueDisplayed: 0.22µF  [0402L]  (hidden comment: GCM155R71C224KE02D)
C8  ValueDisplayed: 0.22µF  [0402L]  (hidden comment: GCM155R71C224KE02D)
C9  ValueDisplayed: 2.2uF  VDC_V: 10V  [FP-GRT155C71A225KE13D_0402-MFG]  (hidden comment: GRT155C71A225KE13D)
C10  ValueDisplayed: 0.22µF  [0402L]  (hidden comment: GCM155R71C224KE02D)
C11  ValueDisplayed: 0.22µF  [0402L]  (hidden comment: GCM155R71C224KE02D)
C12  ValueDisplayed: 0.22µF  [0402L]  (hidden comment: GCM155R71C224KE02D)
C13  value 10µF  [FP-GCM188D70J106ME36D_0603-MFG]  (hidden comment: GCM188D70J106ME36D)
C14  ValueDisplayed: 0.22µF  [0402L]  (hidden comment: GCM155R71C224KE02D)
C15  value 10µF  [FP-GCM188D70J106ME36D_0603-MFG]  (hidden comment: GCM188D70J106ME36D)
C16  ValueDisplayed: 0.22µF  [0402L]  (hidden comment: GCM155R71C224KE02D)
C17  ValueDisplayed: 2.2uF  VDC_V: 10V  [FP-GRT155C71A225KE13D_0402-MFG]  (hidden comment: GRT155C71A225KE13D)
C18  ValueDisplayed: 1uF  [FP-GRT155R70J105KE01D_0402-MFG]  (hidden comment: GRT155R70J105KE01D)
C19  ValueDisplayed: 0.22µF  [0402L]  (hidden comment: GCM155R71C224KE02D)
C20  ValueDisplayed: 2.2uF  VDC_V: 10V  [FP-GRT155C71A225KE13D_0402-MFG]  (hidden comment: GRT155C71A225KE13D)
C21  ValueDisplayed: 0.22µF  [0402L]  (hidden comment: GCM155R71C224KE02D)
C22  ValueDisplayed: 1uF  [FP-GRT155R70J105KE01D_0402-MFG]  (hidden comment: GRT155R70J105KE01D)
C23  value 10µF  [FP-GCM188D70J106ME36D_0603-MFG]  (hidden comment: GCM188D70J106ME36D)
C24  VDC_V: 16V  Cap_F: 4.7µF  [FP-GCJ21BR71C475KA01L_0805-MFG]  (hidden comment: GCJ21BR71C475KA01L)
C25  ValueDisplayed: 0.22µF  [0402L]  (hidden comment: GCM155R71C224KE02D)
C26  ValueDisplayed: 0.22µF  [0402L]  (hidden comment: GCM155R71C224KE02D)
C27  VDC_V: 16V  Cap_F: 4.7µF  [FP-GCJ21BR71C475KA01L_0805-MFG]  (hidden comment: GCJ21BR71C475KA01L)
C28  ValueDisplayed: 0.22µF  [0402L]  (hidden comment: GCM155R71C224KE02D)
C29  ValueDisplayed: 0.22µF  [0402L]  (hidden comment: GCM155R71C224KE02D)
C30  ValueDisplayed: 0.01uF  [0402L]  (hidden comment: GCM155R71E103KA37D)
C44  value 10µF  [FP-GCM188D70J106ME36D_0603-MFG]  (hidden comment: GCM188D70J106ME36D)
C45  ValueDisplayed: 0.01uF  [0402L]  (hidden comment: GCM155R71E103KA37D)
C64  ValueDisplayed: 22uF  [1206_180]  (hidden comment: CGA5L1X7R0J226M160AC)
C80  ValueDisplayed: 22uF  [FP-CGA4J1X7T0J226M125AC_0805-MFG]  (hidden comment: CGA4J1X7T0J226M125AC)
C81  ValueDisplayed: 22uF  [FP-CGA4J1X7T0J226M125AC_0805-MFG]  (hidden comment: CGA4J1X7T0J226M125AC)
C82  ValueDisplayed: 22uF  [FP-CGA4J1X7T0J226M125AC_0805-MFG]  (hidden comment: CGA4J1X7T0J226M125AC)
C83  ValueDisplayed: 22uF  [FP-CGA4J1X7T0J226M125AC_0805-MFG]  (hidden comment: CGA4J1X7T0J226M125AC)
C101  ValueDisplayed: 0.22µF  [0402L]  (hidden comment: GCM155R71C224KE02D)
C103  ValueDisplayed: 22uF  [1206_180]  (hidden comment: CGA5L1X7R0J226M160AC)
C104  ValueDisplayed: 22uF  [FP-CGA4J1X7T0J226M125AC_0805-MFG]  (hidden comment: CGA4J1X7T0J226M125AC)
C109  Cap_F: 10µF  [0805_HV]  (hidden comment: GCM21BR71A106KE22L)
C110  Cap_F: 10µF  [0805_HV]  (hidden comment: GCM21BR71A106KE22L)
C111  ValueDisplayed: 22uF  [FP-CGA4J1X7T0J226M125AC_0805-MFG]  (hidden comment: CGA4J1X7T0J226M125AC)
C112  Cap_F: 10µF  [0805_HV]  (hidden comment: GCM21BR71A106KE22L)
R92  value 0  [FP-HCJ0603ZT0R00_0603-MFG]  (hidden comment: HCJ0603ZT0R00)
R182  value 0  [FP-HCJ0603ZT0R00_0603-MFG]  (hidden comment: HCJ0603ZT0R00)
R183  value 0  [FP-HCJ0603ZT0R00_0603-MFG]  (hidden comment: HCJ0603ZT0R00)

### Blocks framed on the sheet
VBGAP SUPPLY: C6 C18 C22
DC-DC LC FILTERS: C1 C82 C83 C109 R182
1V2_RF SUPPLY: C20 C24 C44 C101
1V2 DIG SUPPLY: C27-C30 C45
3V3_IO SUPPLY: C16 C17 C21

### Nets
CB_REG_1V2: C64.2 R183.1
CB_REG_1V8: C1.2 R182.1
CB_REG_RF_1V2: C103.2 R92.1
GND: C1.1 C4.1 C5.1 C6.2 C7.1 C8.1 C9.1 C10.1 C11.1 C12.1 C13.2 C14.1 C15.2 C16.1 C17.1 C18.1 C19.1 C20.1 C21.1 C22.1 C23.2 C24.1 C25.1 C26.1 C27.1 C28.1 C29.1 C30.2 C44.2 C45.2 C64.1 C80.1 C81.1 C82.1 C83.1 C101.1 C103.1 C104.1 C109.2 C110.2 C111.1 C112.2
RADAR_1P2_RF: C20.2 C24.2 C44.1 C101.2 C104.2 C111.2 C112.1 R92.2
RADAR_1V2: C25.2 C26.2 C27.2 C28.2 C29.2 C30.1 C45.1 C80.2 C81.2 C110.1 R183.2
RADAR_1V4_APLL: C22.2
RADAR_1V4_SYNTH: C18.2
RADAR_1V8: C4.2 C5.2 C7.2 C8.2 C10.2 C11.2 C12.2 C13.1 C14.2 C15.1 C82.2 C83.2 C109.1 R182.2
RADAR_1V_RF_OUT: C9.2 C19.2 C23.1
RADAR_3V3: C16.2 C17.2 C21.2
RADAR_VBGAP: C6.1

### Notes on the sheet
- SUPPLY_DECOUPLING_CAPS
- BB SUPPLY
- VCLK SUPPLY
- VCO_LDO SUPPLY
- PM SUPPLY
- 1P8V IO SUPPLY
- VOUT_PLL SUPPLY
- VOUT_SYNTH SUPPLY
- VNWA SUPPLY
- SRAM SUPPLY
- 1V_RF_OUT SUPPLY
- Design note: Alternate Ferrite bead part for R182,R183, R92 is BLM18KG121TH1D

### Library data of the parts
C1 C64 C103 = CMP-0008770-2: CAP, CERM, 22 uF, 6.3 V, +/- 10%, X7R, AEC-Q200 Grade 1, 1206; Manufacturer: TDK; TaMin_C: -55°C; ESR_ohm: 1.872m; Polarized: N; SizeAreaWB_mm2: 10.92; Value1: 0.001872 ohm; U/M: EA; Value: 22uF; SizeZ_mm: 1.8; SizeX_mm: 3.2; SizeY_mm: 1.6; Value2: 6.3V; SizeArea_mm2: 5.12; CompType: Capacitor; AEC Qualified: Y; Cap_F: 22µF; IRMS_A: 5.30203A; AEC Grade: 1; AEC Category: Q200; TaMax_C: 125°C; INSTALLATION: DNP
C4 C5 C7 C8 C10-C12 C14 C16 C19 C21 C25 C26 C28 C29 C101 = CMP-0078265-1: as C85 on sheet PROC117B_USB_PWR_DC_Jack_Switch
C6 = CMP-0006330-2: CAP, CERM, 0.047 uF, 50 V, +/- 10%, X7R, AEC-Q200 Grade 1, 0402; Manufacturer: TDK; Polarized: N; U/M: EA; Cap_F: 47nF; ESR_ohm: 0.06407; Value1: 0.06407 ohm; VDC_V: 50V; IRMS_A: 646.122mA; TaMin_C: -55°C; TaMax_C: 125°C; Cap_Case: 0402; SizeArea_mm2: 0.5; SizeAreaWB_mm2: 3; SizeX_mm: 1; SizeZ_mm: 0.6; AEC Category: Q200; AEC Qualified: Y
C9 C17 C20 = CMP-0094968-1: Multi-Layer Ceramic Capacitor 2.2uF 10V X7S ±10% 0402 Paper T/R; Manufacturer: Murata; AEC Grade: Grade 1; Cap_F: 2.2µF; SizeZ_mm: 0.7mm; Value: 2.2µF; AEC Qualified: Yes; TempCo: 22%
C13 C15 C23 C44 = CMP-0086534-1: Chip Multilayer Ceramic Capacitors for Automotive; Manufacturer: Murata; Tolerance_%: 20%; SizeZ_mm: 1mm; TempCo: -33+22%; Symbol Name: SYM-GCM188D70J106ME36D; VDC_V: 6.3V; AEC Grade: Grade 1; AEC Qualified: Yes
C18 C22 = CMP-0088425-1: as C3 on sheet PROC117B_xWRL6432_Chip
C24 C27 = CMP-0094778-1: Multilayer Ceramic Capacitors MLCC - SMD/SMT 0805 4.7uF 10%, 16VDC,  X7R 15%; Manufacturer: Murata; AEC Qualified: Yes; Value: 4.7µF; AEC Grade: Grade 1; SizeZ_mm: 1.45mm
C30 C45 = CMP-0006352-2: CAP, CERM, 0.01 uF, 25 V, +/- 10%, X7R, 0402; Manufacturer: MuRata; TaMin_C: -55°C; Polarized: N; SizeAreaWB_mm2: 3; Value1: Unknown; U/M: EA; Value: 0.01uF; TaMax_C: 125°C; SizeZ_mm: 0.6; SizeX_mm: 1; SizeY_mm: 0.5; Cap_Case: 0402; Value2: 25V; CompType: Capacitor; Cap_F: 10nF; AEC Category: Q200
C80-C83 C104 C111 = CMP-0091983-1: 22µF ±20% 6.3V Ceramic Capacitor X7T 0805 (2012 Metric); Manufacturer: TDK; AEC Qualified: Yes; AEC Grade: Grade 1; TempCo: +22/-33%; SizeZ_mm: 1.55mm
C109 C110 C112 = CMP-0008017-2: CAP, CERM, 10 uF, 10 V, +/- 10%, X7R, 0805; Manufacturer: MuRata; TaMin_C: -55°C; Polarized: N; SizeAreaWB_mm2: 6.75; Value1: Unknown; U/M: EA; Value: 10uF; TaMax_C: 125°C; SizeZ_mm: 1.45; SizeX_mm: 2; SizeY_mm: 1.25; Cap_Case: 0805; Value2: 10V; SizeArea_mm2: 2.5; AEC Category: Q200
R92 R182 R183 = CMP-0091690-1: RES 0 OHM JUMPER 1/4W 0603; Manufacturer: Stackpole Electronics; Power_W: 250mW; AEC Grade: Grade 0; AEC Qualified: Yes; SizeZ_mm: 0.7mm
